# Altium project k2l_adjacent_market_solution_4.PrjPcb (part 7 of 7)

## Sheet system_power_03.SchDoc
size 431 x 279 mm; Date: Not shown in title block; ApprovedBy: Not shown in title block; CheckedBy: Not shown in title block; Author: Not shown in title block; CompanyName: Not shown in title block; Engineer: Not shown in title block; Organization: Not shown in title block; Address1: Not shown in title block; Address2: Not shown in title block; Address3: Not shown in title block; Address4: Not shown in title block; DocumentNumber: 36; Revision: Use project parameter SCH_Rev; SheetNumber: 36; SheetTotal: 38; PageSetup: Record=PageOptions¦CenterHorizontal=True¦CenterVertical=True¦PrintScale=1.00¦XCorrection=1.00¦YCorrection=1.00¦PrintKind=0¦BorderSize=5000000¦LeftOffset=0¦BottomOffset=0¦Orientation=2¦PaperLength=1000¦PaperWidth=1000¦Scale=100¦PaperSource=15¦PrintQuality=600¦MediaType=1¦DitherType=10¦PaperKind=Letter¦PrintScaleMode=1
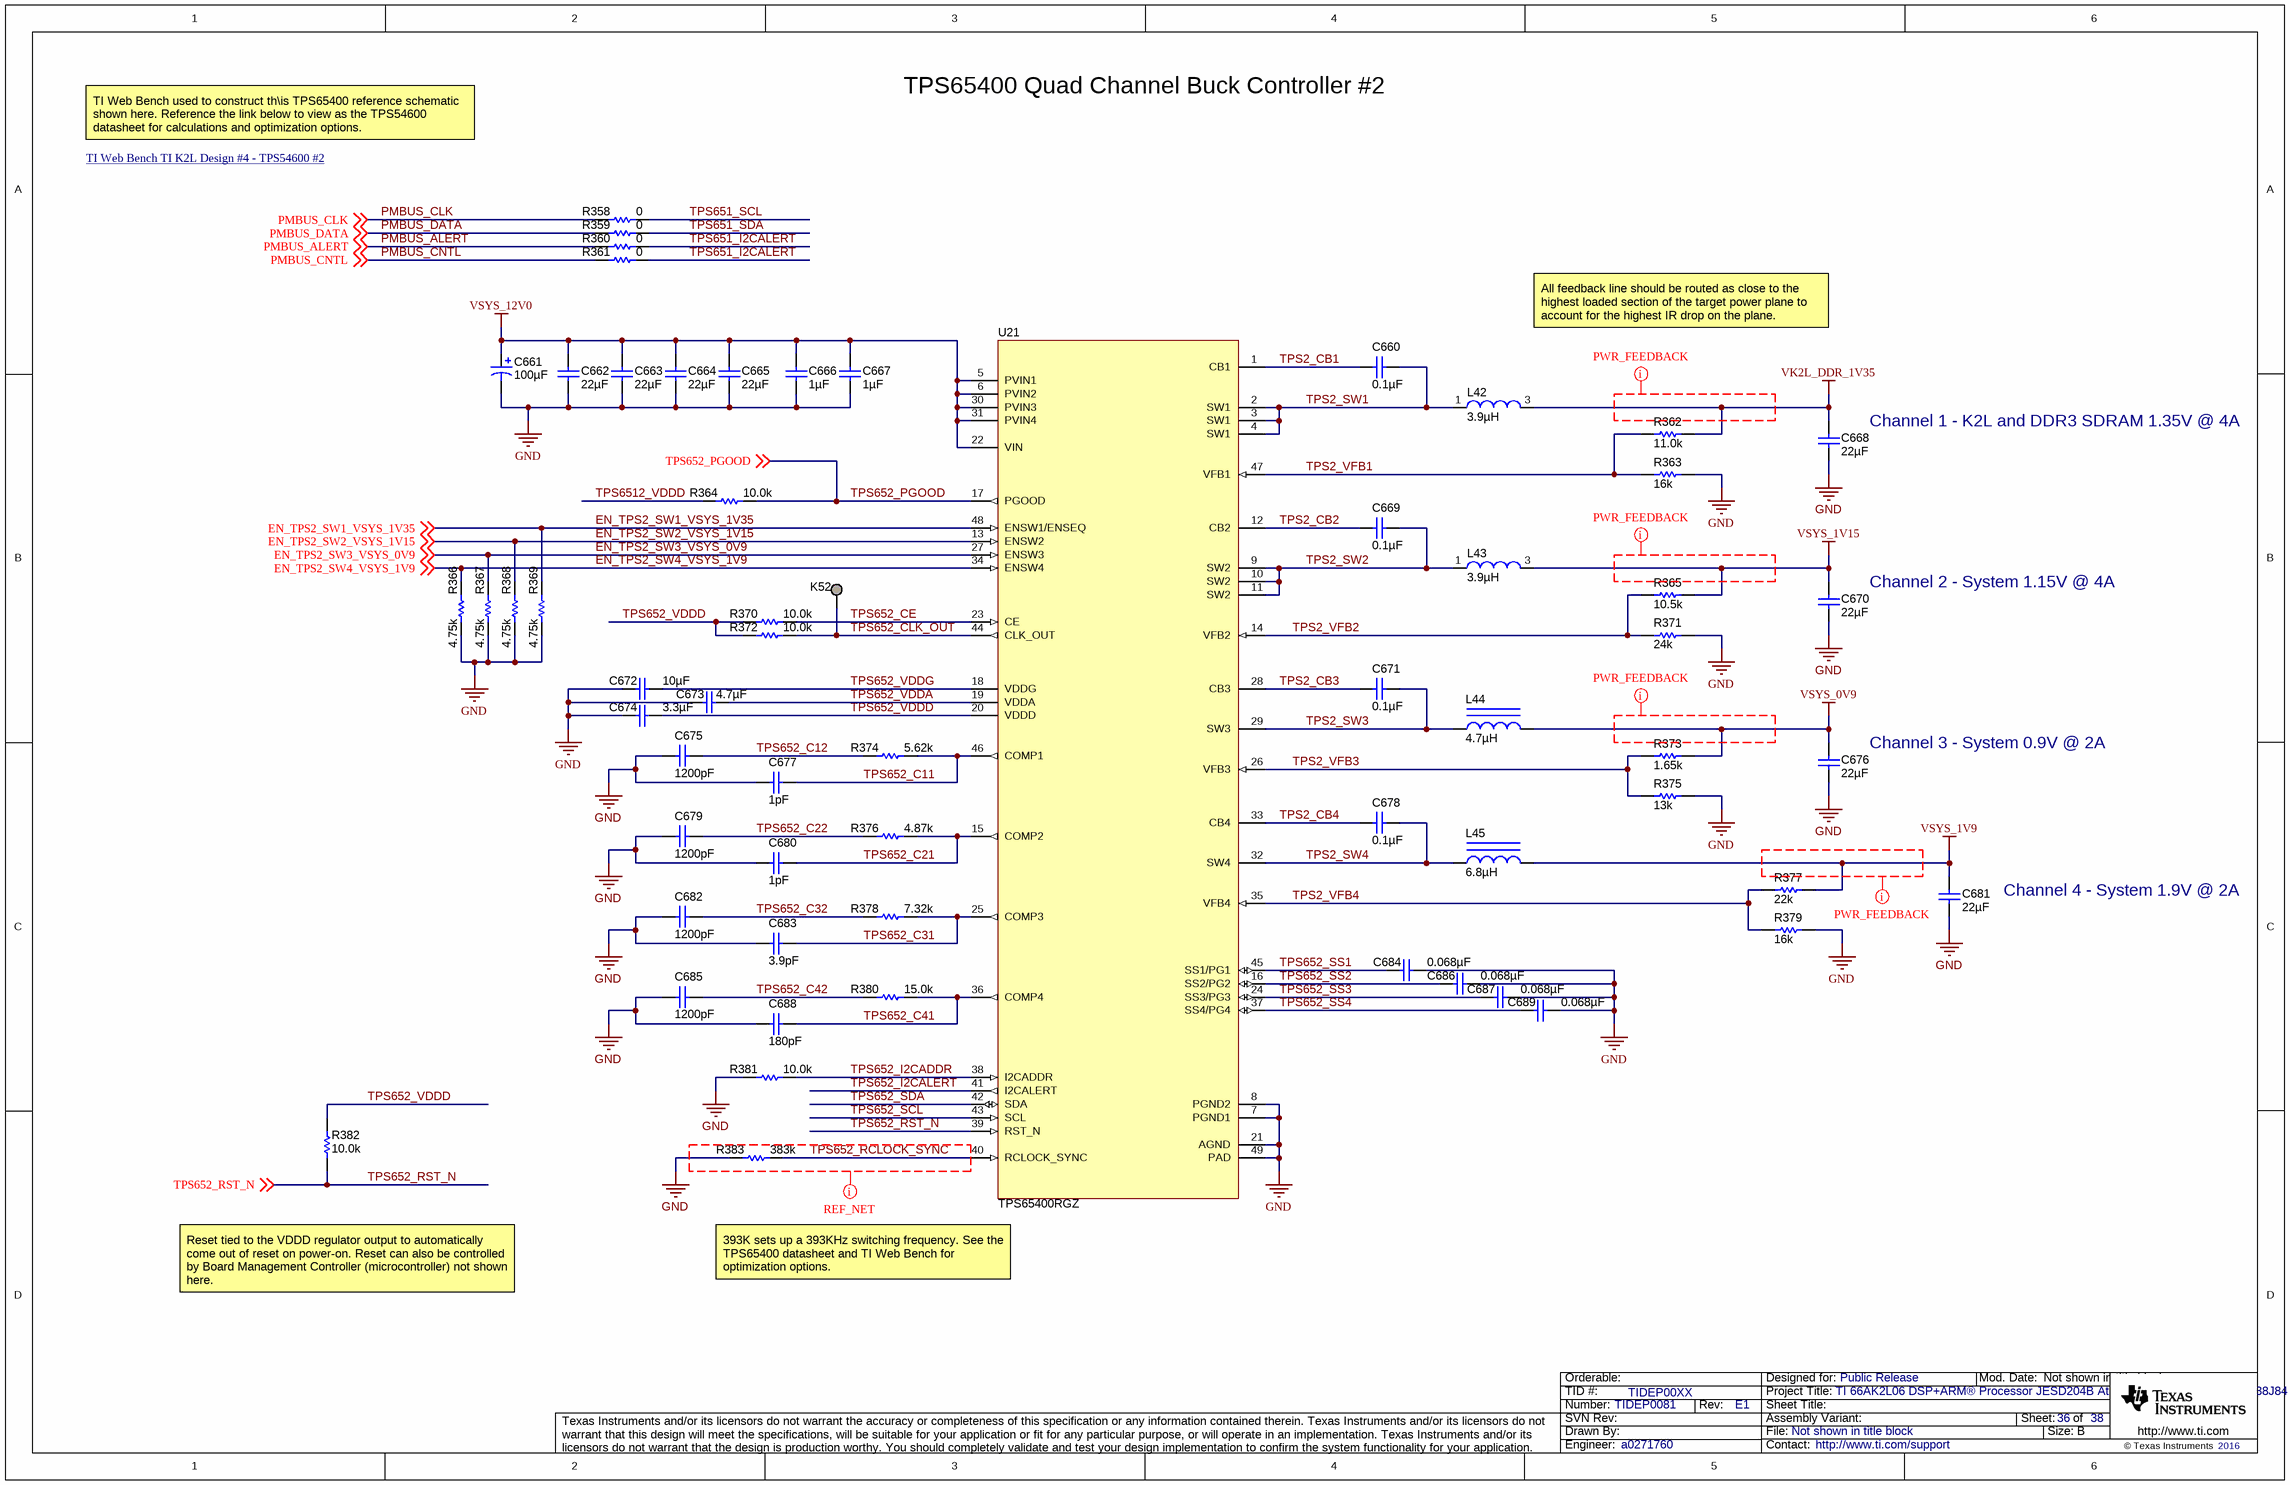
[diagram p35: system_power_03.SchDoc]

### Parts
C660  ValueDisplayed: 0.1µF  [0805_HV]  (hidden comment: 08053C104KAT2A)
C661  ValueDisplayed: 100µF  [6032-28]  (hidden comment: T495C107M006ATE150)
C662  ValueDisplayed: 22µF  [1210_270]  (hidden comment: GRM32ER61E226KE15L)
C663  ValueDisplayed: 22µF  [1210_270]  (hidden comment: GRM32ER61E226KE15L)
C664  ValueDisplayed: 22µF  [1210_270]  (hidden comment: GRM32ER61E226KE15L)
C665  ValueDisplayed: 22µF  [1210_270]  (hidden comment: GRM32ER61E226KE15L)
C666  ValueDisplayed: 1µF  [0603]  (hidden comment: GRM188R61E105KA12D)
C667  ValueDisplayed: 1µF  [0603]  (hidden comment: GRM188R61E105KA12D)
C668  ValueDisplayed: 22µF  [1210_270]  (hidden comment: GRM32ER61E226KE15L)
C669  ValueDisplayed: 0.1µF  [0805_HV]  (hidden comment: 08053C104KAT2A)
C670  ValueDisplayed: 22µF  [1210_270]  (hidden comment: GRM32ER61E226KE15L)
C671  ValueDisplayed: 0.1µF  [0805_HV]  (hidden comment: 08053C104KAT2A)
C672  ValueDisplayed: 10µF  [0603]  (hidden comment: GRM188R61E106MA73D)
C673  ValueDisplayed: 4.7µF  [0603]  (hidden comment: GRM188R61E475KE11D)
C674  ValueDisplayed: 3.3µF  [0603]  (hidden comment: GRM188R61A335KE15D)
C675  ValueDisplayed: 1200pF  [0402]  (hidden comment: GRM155R71H122KA01D)
C676  ValueDisplayed: 22µF  [1210_270]  (hidden comment: GRM32ER61E226KE15L)
C677  ValueDisplayed: 1pF  [0603]  (hidden comment: C0603C109C5GACTU)
C678  ValueDisplayed: 0.1µF  [0805_HV]  (hidden comment: 08053C104KAT2A)
C679  ValueDisplayed: 1200pF  [0402]  (hidden comment: GRM155R71H122KA01D)
C680  ValueDisplayed: 1pF  [0603]  (hidden comment: C0603C109C5GACTU)
C681  ValueDisplayed: 22µF  [1210_270]  (hidden comment: GRM32ER61E226KE15L)
C682  ValueDisplayed: 1200pF  [0402]  (hidden comment: GRM155R71H122KA01D)
C683  ValueDisplayed: 3.9pF  [0402]  (hidden comment: GRM1555C1H3R9CA01D)
C684  ValueDisplayed: 0.068µF  [0402]  (hidden comment: GRM155R61A683KA01D)
C685  ValueDisplayed: 1200pF  [0402]  (hidden comment: GRM155R71H122KA01D)
C686  ValueDisplayed: 0.068µF  [0402]  (hidden comment: GRM155R61A683KA01D)
C687  ValueDisplayed: 0.068µF  [0402]  (hidden comment: GRM155R61A683KA01D)
C688  ValueDisplayed: 180pF  [0402]  (hidden comment: GRM1555C1H181JA01D)
C689  ValueDisplayed: 0.068µF  [0402]  (hidden comment: GRM155R61A683KA01D)
K52  TESTPOINT  [TESTPOINT]  (value not drawn)  (no BOM)
L42  ValueDisplayed: 3.9µH  [WE-TPC_8043]  (hidden comment: 744071039)
L43  ValueDisplayed: 3.9µH  [WE-TPC_8043]  (hidden comment: 744071039)
L44  ValueDisplayed: 4.7µH  [IHSM5832]  (hidden comment: IHSM5832ER4R7L)
L45  ValueDisplayed: 6.8µH  [SRN6045]  (hidden comment: SRN6045-6R8Y)
R358  ValueDisplayed: 0  [0402]  (hidden comment: CRCW04020000Z0ED)
R359  ValueDisplayed: 0  [0402]  (hidden comment: CRCW04020000Z0ED)
R360  ValueDisplayed: 0  [0402]  (hidden comment: CRCW04020000Z0ED)
R361  ValueDisplayed: 0  [0402]  (hidden comment: CRCW04020000Z0ED)
R362  ValueDisplayed: 11.0k  [0402]  (hidden comment: CRCW040211K0FKED)
R363  ValueDisplayed: 16k  [0402]  (hidden comment: CRCW040216K0JNED)
R364  ValueDisplayed: 10.0k  [0402]  (hidden comment: CRCW040210K0FKED)
R365  ValueDisplayed: 10.5k  [0402]  (hidden comment: CRCW040210K5FKED)
R366  ValueDisplayed: 4.75k  [0402]  (hidden comment: CRCW04024K75FKED)
R367  ValueDisplayed: 4.75k  [0402]  (hidden comment: CRCW04024K75FKED)
R368  ValueDisplayed: 4.75k  [0402]  (hidden comment: CRCW04024K75FKED)
R369  ValueDisplayed: 4.75k  [0402]  (hidden comment: CRCW04024K75FKED)
R370  ValueDisplayed: 10.0k  [0402]  (hidden comment: CRCW040210K0FKED)
R371  ValueDisplayed: 24k  [0402]  (hidden comment: CRCW040224K0JNED)
R372  ValueDisplayed: 10.0k  [0402]  (hidden comment: CRCW040210K0FKED)
R373  ValueDisplayed: 1.65k  [0402]  (hidden comment: CRCW04021K65FKED)
R374  ValueDisplayed: 5.62k  [0402]  (hidden comment: CRCW04025K62FKED)
R375  ValueDisplayed: 13k  [0402]  (hidden comment: CRCW040213K0JNED)
R376  ValueDisplayed: 4.87k  [0402]  (hidden comment: CRCW04024K87FKED)
R377  ValueDisplayed: 22k  [0402]  (hidden comment: CRCW040222K0JNED)
R378  ValueDisplayed: 7.32k  [0402]  (hidden comment: CRCW04027K32FKED)
R379  ValueDisplayed: 16k  [0402]  (hidden comment: CRCW040216K0JNED)
R380  ValueDisplayed: 15.0k  [0402]  (hidden comment: CRCW040215K0FKED)
R381  ValueDisplayed: 10.0k  [0402]  (hidden comment: CRCW040210K0FKED)
R382  ValueDisplayed: 10.0k  [0402]  (hidden comment: CRCW040210K0FKED)
R383  ValueDisplayed: 383k  [0402]  (hidden comment: CRCW0402383KFKED)
U21  TPS65400RGZ  [RGZ0048G]

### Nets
GND: C661.2(-) C662.2 C663.2 C664.2 C665.2 C666.2 C667.2 C668.2 C670.2 C672.2 C673.1 C674.1 C675.2 C676.2 C677.2 C679.2 C680.2 C681.2 C682.2 C683.2 C684.2 C685.2 C686.2 C687.2 C688.2 C689.2 R363.2 R366.1 R367.1 R368.1 R369.1 R371.2 R375.2 R379.2 R381.1 R383.1 U21.7(PGND1) U21.8(PGND2) U21.21(AGND) U21.49(PAD)  [project net DAC_OUT0N_T1]
VK2L_DDR_1V35: C668.1 L42.3 R362.2
VSYS_0V9: C676.1 L44.2 R373.2
VSYS_1V9: C681.1 L45.2 R377.2
VSYS_1V15: C670.1 L43.3 R365.2
VSYS_12V0: C661.1(+) C662.1 C663.1 C664.1 C665.1 C666.1 C667.1 U21.5(PVIN1) U21.6(PVIN2) U21.22(VIN) U21.30(PVIN3) U21.31(PVIN4)
EN_TPS2_SW1_VSYS_1V35: R369.2 U21.48(ENSW1/ENSEQ) ; off-sheet EN_TPS2_SW1_VSYS_1V35
EN_TPS2_SW2_VSYS_1V15: R368.2 U21.13(ENSW2) ; off-sheet EN_TPS2_SW2_VSYS_1V15
EN_TPS2_SW3_VSYS_0V9: R367.2 U21.27(ENSW3) ; off-sheet EN_TPS2_SW3_VSYS_0V9
EN_TPS2_SW4_VSYS_1V9: R366.2 U21.34(ENSW4) ; off-sheet EN_TPS2_SW4_VSYS_1V9
PMBUS_ALERT: R360.1 ; off-sheet PMBUS_ALERT
PMBUS_CLK: R358.1 ; off-sheet PMBUS_CLK
PMBUS_CNTL: R361.1 ; off-sheet PMBUS_CNTL
PMBUS_DATA: R359.1 ; off-sheet PMBUS_DATA
TPS2_CB1: C660.2 U21.1(CB1)
TPS2_CB2: C669.2 U21.12(CB2)
TPS2_CB3: C671.2 U21.28(CB3)
TPS2_CB4: C678.2 U21.33(CB4)
TPS2_SW1: C660.1 L42.1 U21.2(SW1) U21.3(SW1) U21.4(SW1)
TPS2_SW2: C669.1 L43.1 U21.9(SW2) U21.10(SW2) U21.11(SW2)
TPS2_SW3: C671.1 L44.1 U21.29(SW3)
TPS2_SW4: C678.1 L45.1 U21.32(SW4)
TPS2_VFB1: R362.1 R363.1 U21.47(VFB1)
TPS2_VFB2: R365.1 R371.1 U21.14(VFB2)
TPS2_VFB3: R373.1 R375.1 U21.26(VFB3)
TPS2_VFB4: R377.1 R379.1 U21.35(VFB4)
TPS651_I2CALERT: R360.2 R361.2
TPS651_SCL: R358.2
TPS651_SDA: R359.2
TPS652_C11: C677.1 R374.2 U21.46(COMP1)
TPS652_C12: C675.1 R374.1
TPS652_C21: C680.1 R376.2 U21.15(COMP2)
TPS652_C22: C679.1 R376.1
TPS652_C31: C683.1 R378.2 U21.25(COMP3)
TPS652_C32: C682.1 R378.1
TPS652_C41: C688.1 R380.2 U21.36(COMP4)
TPS652_C42: C685.1 R380.1
TPS652_CE: R370.2 U21.23(CE)
TPS652_CLK_OUT: K52.1 R372.2 U21.44(CLK_OUT)
TPS652_I2CADDR: R381.2 U21.38(I2CADDR)
TPS652_I2CALERT: U21.41(I2CALERT)
TPS652_PGOOD: R364.2 U21.17(PGOOD) ; off-sheet TPS652_PGOOD
TPS652_RCLOCK_SYNC: R383.2 U21.40(RCLOCK_SYNC)
TPS652_RST_N: R382.1 U21.39(RST_N) ; off-sheet TPS652_RST_N
TPS652_SCL: U21.43(SCL)
TPS652_SDA: U21.42(SDA)
TPS652_SS1: C684.1 U21.45(SS1/PG1)
TPS652_SS2: C686.1 U21.16(SS2/PG2)
TPS652_SS3: C687.1 U21.24(SS3/PG3)
TPS652_SS4: C689.1 U21.37(SS4/PG4)
TPS652_VDDA: C673.2 U21.19(VDDA)
TPS652_VDDD: C674.2 R370.1 R372.1 R382.2 U21.20(VDDD)
TPS652_VDDG: C672.1 U21.18(VDDG)
TPS6512_VDDD: R364.1

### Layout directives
net class Undefined: (no net found under the mark), TPS652_RCLOCK_SYNC

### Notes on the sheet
- TPS65400 Quad Channel Buck Controller #2
- TI Web Bench used to construct th\is TPS65400 reference schematic shown here. Reference the link below to view as the TPS54600 datasheet for calculations and optimization options.
- TI Web Bench TI K2L Design #4 - TPS54600 #2 <https://webench.ti.com/wb5/OpenPublicSharedProject.jsp?id=085F10CA9CD21835&s=c>
- All feedback line should be routed as close to the highest loaded section of the target power plane to account for the highest IR drop on the plane.
- (near C668) Channel 1 - K2L and DDR3 SDRAM 1.35V @ 4A
- (near C670) Channel 2 - System 1.15V @ 4A
- (near C676) Channel 3 - System 0.9V @ 2A
- Channel 4 - System 1.9V @ 2A
- Reset tied to the VDDD regulator output to automatically come out of reset on power-on. Reset can also be controlled by Board Management Controller (microcontroller) not shown here.
- 393K sets up a 393KHz switching frequency. See the TPS65400 datasheet and TI Web Bench for optimization options.

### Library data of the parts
C660 C669 C671 C678 = 08053C104KAT2A: CAP, CERM, 0.1 µF, 25 V, +/- 10%, X7R, 0805; Manufacturer: AVX; Polarized: N; CompType: Capacitor; Value: 0.1uF; U/M: EA; Cap_F: 0.0000001; Tolerance_%: 10; ESR_ohm: 0.28; Value1: 0.28 ohm; VDC_V: 25; Value2: 25V; TaMin_C: -55; TaMax_C: 125; Cap_Case: 0805; SizeArea_mm2: 2.5; SizeAreaWB_mm2: 6.75; SizeX_mm: 2; SizeY_mm: 1.25; SizeZ_mm: 1.45; AEC Category: Q200
C661 = T495C107M006ATE150: CAP, TA, 100 µF, 6.3 V, +/- 20%, 0.15 ohm, SMD; Manufacturer: Kemet; Polarized: Y; CompType: Capacitor; Value: 100uF; U/M: EA; Cap_F: 0.0001; Tolerance_%: 20; VDC_V: 6.3; Value2: 6.3V; ESR_ohm: 0.15; IRMS_A: 0.77; TaMin_C: -55; TaMax_C: 125; Cap_Case: C; AEC Category: Q200
C662-C665 C668 C670 C676 C681 = GRM32ER61E226KE15L: CAP, CERM, 22 µF, 25 V, +/- 10%, X5R, 1210; Manufacturer: MuRata; Polarized: N; CompType: Capacitor; Value: 22uF; U/M: EA; Cap_F: 0.000022; Tolerance_%: 10; ESR_ohm: 0.002; Value1: 0.002 ohm; VDC_V: 25; Value2: 25V; IRMS_A: 3.67; TaMin_C: -55; TaMax_C: 85; Cap_Case: 1210; SizeArea_mm2: 8; SizeAreaWB_mm2: 14.7; SizeX_mm: 3.2; SizeY_mm: 2.5; SizeZ_mm: 2.7; AEC Category: Q200
C666 C667 = GRM188R61E105KA12D: CAP, CERM, 1 µF, 25 V, +/- 10%, X5R, 0603; Manufacturer: MuRata; Polarized: N; CompType: Capacitor; Value: 1uF; U/M: EA; Cap_F: 0.000001; Tolerance_%: 10; Value1: Unknown; VDC_V: 25; Value2: 25V; TaMin_C: -55; TaMax_C: 85; SizeArea_mm2: 1.28; SizeAreaWB_mm2: 4.68; SizeX_mm: 1.6; SizeY_mm: 0.8; SizeZ_mm: 1; AEC Category: Q200
C672 = GRM188R61E106MA73D: CAP, CERM, 10 µF, 25 V, +/- 20%, X5R, 0603; Manufacturer: MuRata; Polarized: N; CompType: Capacitor; Value: 10uF; U/M: EA; Cap_F: 0.00001; Tolerance_%: 20; Value1: Unknown; VDC_V: 25; Value2: 25V; TaMin_C: -55; TaMax_C: 85; SizeArea_mm2: 1.28; SizeAreaWB_mm2: 4.68; SizeX_mm: 1.6; SizeY_mm: 0.8; SizeZ_mm: 1; AEC Category: Q200
C673 = GRM188R61E475KE11D: CAP, CERM, 4.7 µF, 25 V, +/- 10%, X5R, 0603; Manufacturer: MuRata; Polarized: N; CompType: Capacitor; Value: 4.7uF; U/M: EA; Cap_F: 0.0000047; Tolerance_%: 10; Value1: Unknown; VDC_V: 25; Value2: 25V; TaMin_C: -55; TaMax_C: 85; SizeArea_mm2: 1.28; SizeAreaWB_mm2: 4.68; SizeX_mm: 1.6; SizeY_mm: 0.8; SizeZ_mm: 1; AEC Category: Q200
C674 = GRM188R61A335KE15D: CAP, CERM, 3.3 µF, 10 V, +/- 10%, X5R, 0603; Manufacturer: MuRata; Polarized: N; CompType: Capacitor; Value: 3.3uF; U/M: EA; Cap_F: 0.0000033; Tolerance_%: 10; ESR_ohm: 0.005; Value1: 0.005 ohm; Value2: 10V; IRMS_A: 1.7; TaMin_C: -55; TaMax_C: 85; SizeArea_mm2: 1.28; SizeAreaWB_mm2: 4.68; SizeX_mm: 1.6; SizeY_mm: 0.8; SizeZ_mm: 1; AEC Category: Q200
C675 C679 C682 C685 = GRM155R71H122KA01D: CAP, CERM, 1200 pF, 50 V, +/- 10%, X7R, 0402; Manufacturer: MuRata; Polarized: N; CompType: Capacitor; Value: 1200pF; U/M: EA; Cap_F: 0.0000000012; Tolerance_%: 10; Value1: Unknown; VDC_V: 50; Value2: 50V; TaMin_C: -55; TaMax_C: 125; SizeArea_mm2: 0.5; SizeAreaWB_mm2: 3; SizeX_mm: 1; SizeZ_mm: 0.6; AEC Category: Q200
C677 C680 = C0603C109C5GACTU: CAP, CERM, 1 pF, 50 V, +/- 25%, C0G/NP0, 0603; Manufacturer: Kemet; Polarized: N; CompType: Capacitor; Value: 1pF; U/M: EA; Cap_F: 0.000000000001; Tolerance_%: 25; Value1: Unknown; VDC_V: 50; Value2: 50V; TaMin_C: -55; TaMax_C: 125; SizeArea_mm2: 1.28; SizeAreaWB_mm2: 4.68; SizeX_mm: 1.6; SizeY_mm: 0.8; SizeZ_mm: 1; AEC Category: Q200
C683 = GRM1555C1H3R9CA01D: CAP, CERM, 3.9 pF, 50 V, +/- 5%, C0G/NP0, 0402; Manufacturer: MuRata; Polarized: N; CompType: Capacitor; Value: 3.9pF; U/M: EA; Cap_F: 0.0000000000039; Tolerance_%: 5; Value1: Unknown; VDC_V: 50; Value2: 50V; TaMin_C: -55; TaMax_C: 125; SizeArea_mm2: 0.5; SizeAreaWB_mm2: 3; SizeX_mm: 1; SizeZ_mm: 0.6; AEC Category: Q200
C684 C686 C687 C689 = GRM155R61A683KA01D: CAP, CERM, 0.068 µF, 10 V, +/- 10%, X5R, 0402; Manufacturer: MuRata; Polarized: N; CompType: Capacitor; Value: 0.068uF; U/M: EA; Cap_F: 0.000000068; Tolerance_%: 10; Value1: Unknown; Value2: 10V; TaMin_C: -55; TaMax_C: 85; SizeArea_mm2: 0.5; SizeAreaWB_mm2: 3; SizeX_mm: 1; SizeZ_mm: 0.6; AEC Category: Q200
C688 = GRM1555C1H181JA01D: CAP, CERM, 180 pF, 50 V, +/- 5%, C0G/NP0, 0402; Manufacturer: MuRata; Polarized: N; CompType: Capacitor; Value: 180pF; U/M: EA; Cap_F: 0.00000000018; Tolerance_%: 5; Value1: Unknown; VDC_V: 50; Value2: 50V; TaMin_C: -55; TaMax_C: 125; SizeArea_mm2: 0.5; SizeAreaWB_mm2: 3; SizeX_mm: 1; SizeZ_mm: 0.6; AEC Category: Q200
K52 = TESTPOINT: TEST POINT.  No entry in BOM.
L42 L43 = 744071039: Inductor, Shielded Drum Core, Metal Composite, 3.9 µH, 4.9 A, 0.013 ohm, SMD; Manufacturer: Wurth Elektronik; SymbolCreator: a0411947; Ind_H: 3.9E-6; Value: 3.9uH; Imax_A: 4.9; Irms: 4.9A @ 40C rise; Isat: 5A @ 35% inductance drop; DCR_ohm: 0.013; Value2: 4.9A; AEC Category: Q200
L44 = IHSM5832ER4R7L: Inductor, Shielded Drum Core, Ferrite, 4.7 µH, 2.8 A, 0.023 ohm, SMD; Manufacturer: Vishay-Dale; Value: 4.7uH; Ind_H: 4.7E-6; Imax_A: 2.8; Irms: 7.4A @ 40C rise; Isat: 2.8A @ 5% inductance drop; DCR_ohm: 0.023; Value2: 2.8A; AEC Category: Q200
L45 = SRN6045-6R8Y: Inductor, Drum Core, Ferrite, 6.8 µH, 2.8 A, 0.0473 ohm, SMD; Manufacturer: Bourns; Value: 6.8uH; Ind_H: 6.8E-6; Imax_A: 2.8; Irms: 2.8A @ 40C rise; Isat: 3.8A @ 30% inductance drop; DCR_ohm: 0.0473; Value2: 2.8A; AEC Category: Q200
R358-R361 = CRCW04020000Z0ED: RES, 0, 5%, 0.063 W, 0402; Manufacturer: Vishay-Dale; CompType: Resistor; Value: 0; Value_Code: 0000; Tolerance_%: 5; Power_W: 0.063; Value2: 0.063W; VDC_V: 50; TempCo: 200 ppm/C; SizeArea_mm2: 0.5; SizeX_mm: 1; SizeZ_mm: 0.6; EIA_Code: E24; U/M: EA; AEC Category: Q200
R362 = CRCW040211K0FKED: RES, 11.0 k, 1%, 0.063 W, 0402; Manufacturer: Vishay-Dale; CompType: Resistor; Value: 11.0k; Res_ohm: 11000; Value_Code: 11k0; Tolerance_%: 1; Power_W: 0.063; Value2: 0.063W; VDC_V: 50; TempCo: 100 ppm/C; SizeArea_mm2: 0.5; SizeZ_mm: 0.6; EIA_Code: E96; U/M: EA; AEC Category: Q200
R363 R379 = CRCW040216K0JNED: RES, 16 k, 5%, 0.063 W, 0402; Manufacturer: Vishay-Dale; CompType: Resistor; Value: 16k; Res_ohm: 16000; Value_Code: 16k0; Tolerance_%: 5; Power_W: 0.063; Value2: 0.063W; VDC_V: 50; TempCo: 200 ppm/C; SizeArea_mm2: 0.5; SizeX_mm: 1; SizeZ_mm: 0.6; EIA_Code: E24; U/M: EA; AEC Category: Q200
R364 R370 R372 R381 R382 = CRCW040210K0FKED: RES, 10.0 k, 1%, 0.063 W, 0402; Manufacturer: Vishay-Dale; CompType: Resistor; Value: 10.0k; Res_ohm: 10000; Value_Code: 10k0; Tolerance_%: 1; Power_W: 0.063; Value2: 0.063W; VDC_V: 50; TempCo: 100 ppm/C; EIA_Code: E96; U/M: EA
R365 = CRCW040210K5FKED: RES, 10.5 k, 1%, 0.063 W, 0402; Manufacturer: Vishay-Dale; CompType: Resistor; Value: 10.5k; Res_ohm: 10500; Value_Code: 10k5; Tolerance_%: 1; Power_W: 0.063; Value2: 0.063W; VDC_V: 50; TempCo: 100 ppm/C; SizeArea_mm2: 0.5; SizeZ_mm: 0.6; EIA_Code: E96; U/M: EA; AEC Category: Q200
R366-R369 = CRCW04024K75FKED: RES, 4.75 k, 1%, 0.063 W, 0402; Manufacturer: Vishay-Dale; CompType: Resistor; Value: 4.75k; Res_ohm: 4750; Value_Code: 4k75; Tolerance_%: 1; Power_W: 0.063; Value2: 0.063W; VDC_V: 50; TempCo: 100 ppm/C; EIA_Code: E96; U/M: EA
R371 = CRCW040224K0JNED: RES, 24 k, 5%, 0.063 W, 0402; Manufacturer: Vishay-Dale; CompType: Resistor; Value: 24k; Res_ohm: 24000; Value_Code: 24k0; Tolerance_%: 5; Power_W: 0.063; Value2: 0.063W; VDC_V: 50; TempCo: 200 ppm/C; SizeArea_mm2: 0.5; SizeX_mm: 1; SizeZ_mm: 0.6; EIA_Code: E24; U/M: EA; AEC Category: Q200
R373 = CRCW04021K65FKED: RES, 1.65 k, 1%, 0.063 W, 0402; Manufacturer: Vishay-Dale; CompType: Resistor; Value: 1.65k; Res_ohm: 1650; Value_Code: 1k65; Tolerance_%: 1; Power_W: 0.063; Value2: 0.063W; VDC_V: 50; TempCo: 100 ppm/C; SizeArea_mm2: 0.5; SizeZ_mm: 0.6; EIA_Code: E96; U/M: EA; AEC Category: Q200
R374 = CRCW04025K62FKED: RES, 5.62 k, 1%, 0.063 W, 0402; Manufacturer: Vishay-Dale; CompType: Resistor; Value: 5.62k; Res_ohm: 5620; Value_Code: 5k62; Tolerance_%: 1; Power_W: 0.063; Value2: 0.063W; VDC_V: 50; TempCo: 100 ppm/C; SizeArea_mm2: 0.5; SizeZ_mm: 0.6; EIA_Code: E96; U/M: EA; AEC Category: Q200
R375 = CRCW040213K0JNED: RES, 13 k, 5%, 0.063 W, 0402; Manufacturer: Vishay-Dale; CompType: Resistor; Value: 13k; Res_ohm: 13000; Value_Code: 13k0; Tolerance_%: 5; Power_W: 0.063; Value2: 0.063W; VDC_V: 50; TempCo: 200 ppm/C; SizeArea_mm2: 0.5; SizeX_mm: 1; SizeZ_mm: 0.6; EIA_Code: E24; U/M: EA; AEC Category: Q200
R376 = CRCW04024K87FKED: RES, 4.87 k, 1%, 0.063 W, 0402; Manufacturer: Vishay-Dale; CompType: Resistor; Value: 4.87k; Res_ohm: 4870; Value_Code: 4k87; Tolerance_%: 1; Power_W: 0.063; Value2: 0.063W; VDC_V: 50; TempCo: 100 ppm/C; SizeArea_mm2: 0.5; SizeZ_mm: 0.6; EIA_Code: E96; U/M: EA; AEC Category: Q200
R377 = CRCW040222K0JNED: RES, 22 k, 5%, 0.063 W, 0402; Manufacturer: Vishay-Dale; CompType: Resistor; Value: 22k; Res_ohm: 22000; Value_Code: 22k0; Tolerance_%: 5; Power_W: 0.063; Value2: 0.063W; VDC_V: 50; TempCo: 200 ppm/C; SizeArea_mm2: 0.5; SizeX_mm: 1; SizeZ_mm: 0.6; EIA_Code: E24; U/M: EA; AEC Category: Q200
R378 = CRCW04027K32FKED: RES, 7.32 k, 1%, 0.063 W, 0402; Manufacturer: Vishay-Dale; CompType: Resistor; Value: 7.32k; Res_ohm: 7320; Value_Code: 7k32; Tolerance_%: 1; Power_W: 0.063; Value2: 0.063W; VDC_V: 50; TempCo: 100 ppm/C; SizeArea_mm2: 0.5; SizeZ_mm: 0.6; EIA_Code: E96; U/M: EA; AEC Category: Q200
R380 = CRCW040215K0FKED: RES, 15.0 k, 1%, 0.063 W, 0402; Manufacturer: Vishay-Dale; CompType: Resistor; Value: 15.0k; Res_ohm: 15000; Value_Code: 15k0; Tolerance_%: 1; Power_W: 0.063; Value2: 0.063W; VDC_V: 50; TempCo: 100 ppm/C; SizeArea_mm2: 0.5; SizeZ_mm: 0.6; EIA_Code: E96; U/M: EA; AEC Category: Q200
R383 = CRCW0402383KFKED: RES, 383 k, 1%, 0.063 W, 0402; Manufacturer: Vishay-Dale; CompType: Resistor; Value: 383k; Res_ohm: 383000; Tolerance_%: 1; Power_W: 0.063; Value2: 0.063W; VDC_V: 50; TempCo: 100 ppm/C; SizeArea_mm2: 0.5; SizeZ_mm: 0.6; EIA_Code: E96; U/M: EA; AEC Category: Q200
U21 = TPS65400RGZ: 4.5V TO 18V INPUT FLEXIBLE POWER MANAGEMENT UNIT WITH PMBus/ I2C AND INTEGRATED SEQUENCING, RGZ0048G; Manufacturer: Texas Instruments; SymbolCreator: a0411947; CompType: IC; U/M: EA

## Sheet system_power_04.SchDoc
size 431 x 279 mm; Date: Not shown in title block; ApprovedBy: Not shown in title block; CheckedBy: Not shown in title block; Author: Not shown in title block; CompanyName: Not shown in title block; Engineer: Not shown in title block; Organization: Not shown in title block; Address1: Not shown in title block; Address2: Not shown in title block; Address3: Not shown in title block; Address4: Not shown in title block; DocumentNumber: 37; Revision: Use project parameter SCH_Rev; SheetNumber: 37; SheetTotal: 38; PageSetup: Record=PageOptions¦CenterHorizontal=True¦CenterVertical=True¦PrintScale=1.00¦XCorrection=1.00¦YCorrection=1.00¦PrintKind=0¦BorderSize=5000000¦LeftOffset=0¦BottomOffset=0¦Orientation=2¦PaperLength=1000¦PaperWidth=1000¦Scale=100¦PaperSource=15¦PrintQuality=600¦MediaType=1¦DitherType=10¦PaperKind=Letter¦PrintScaleMode=1
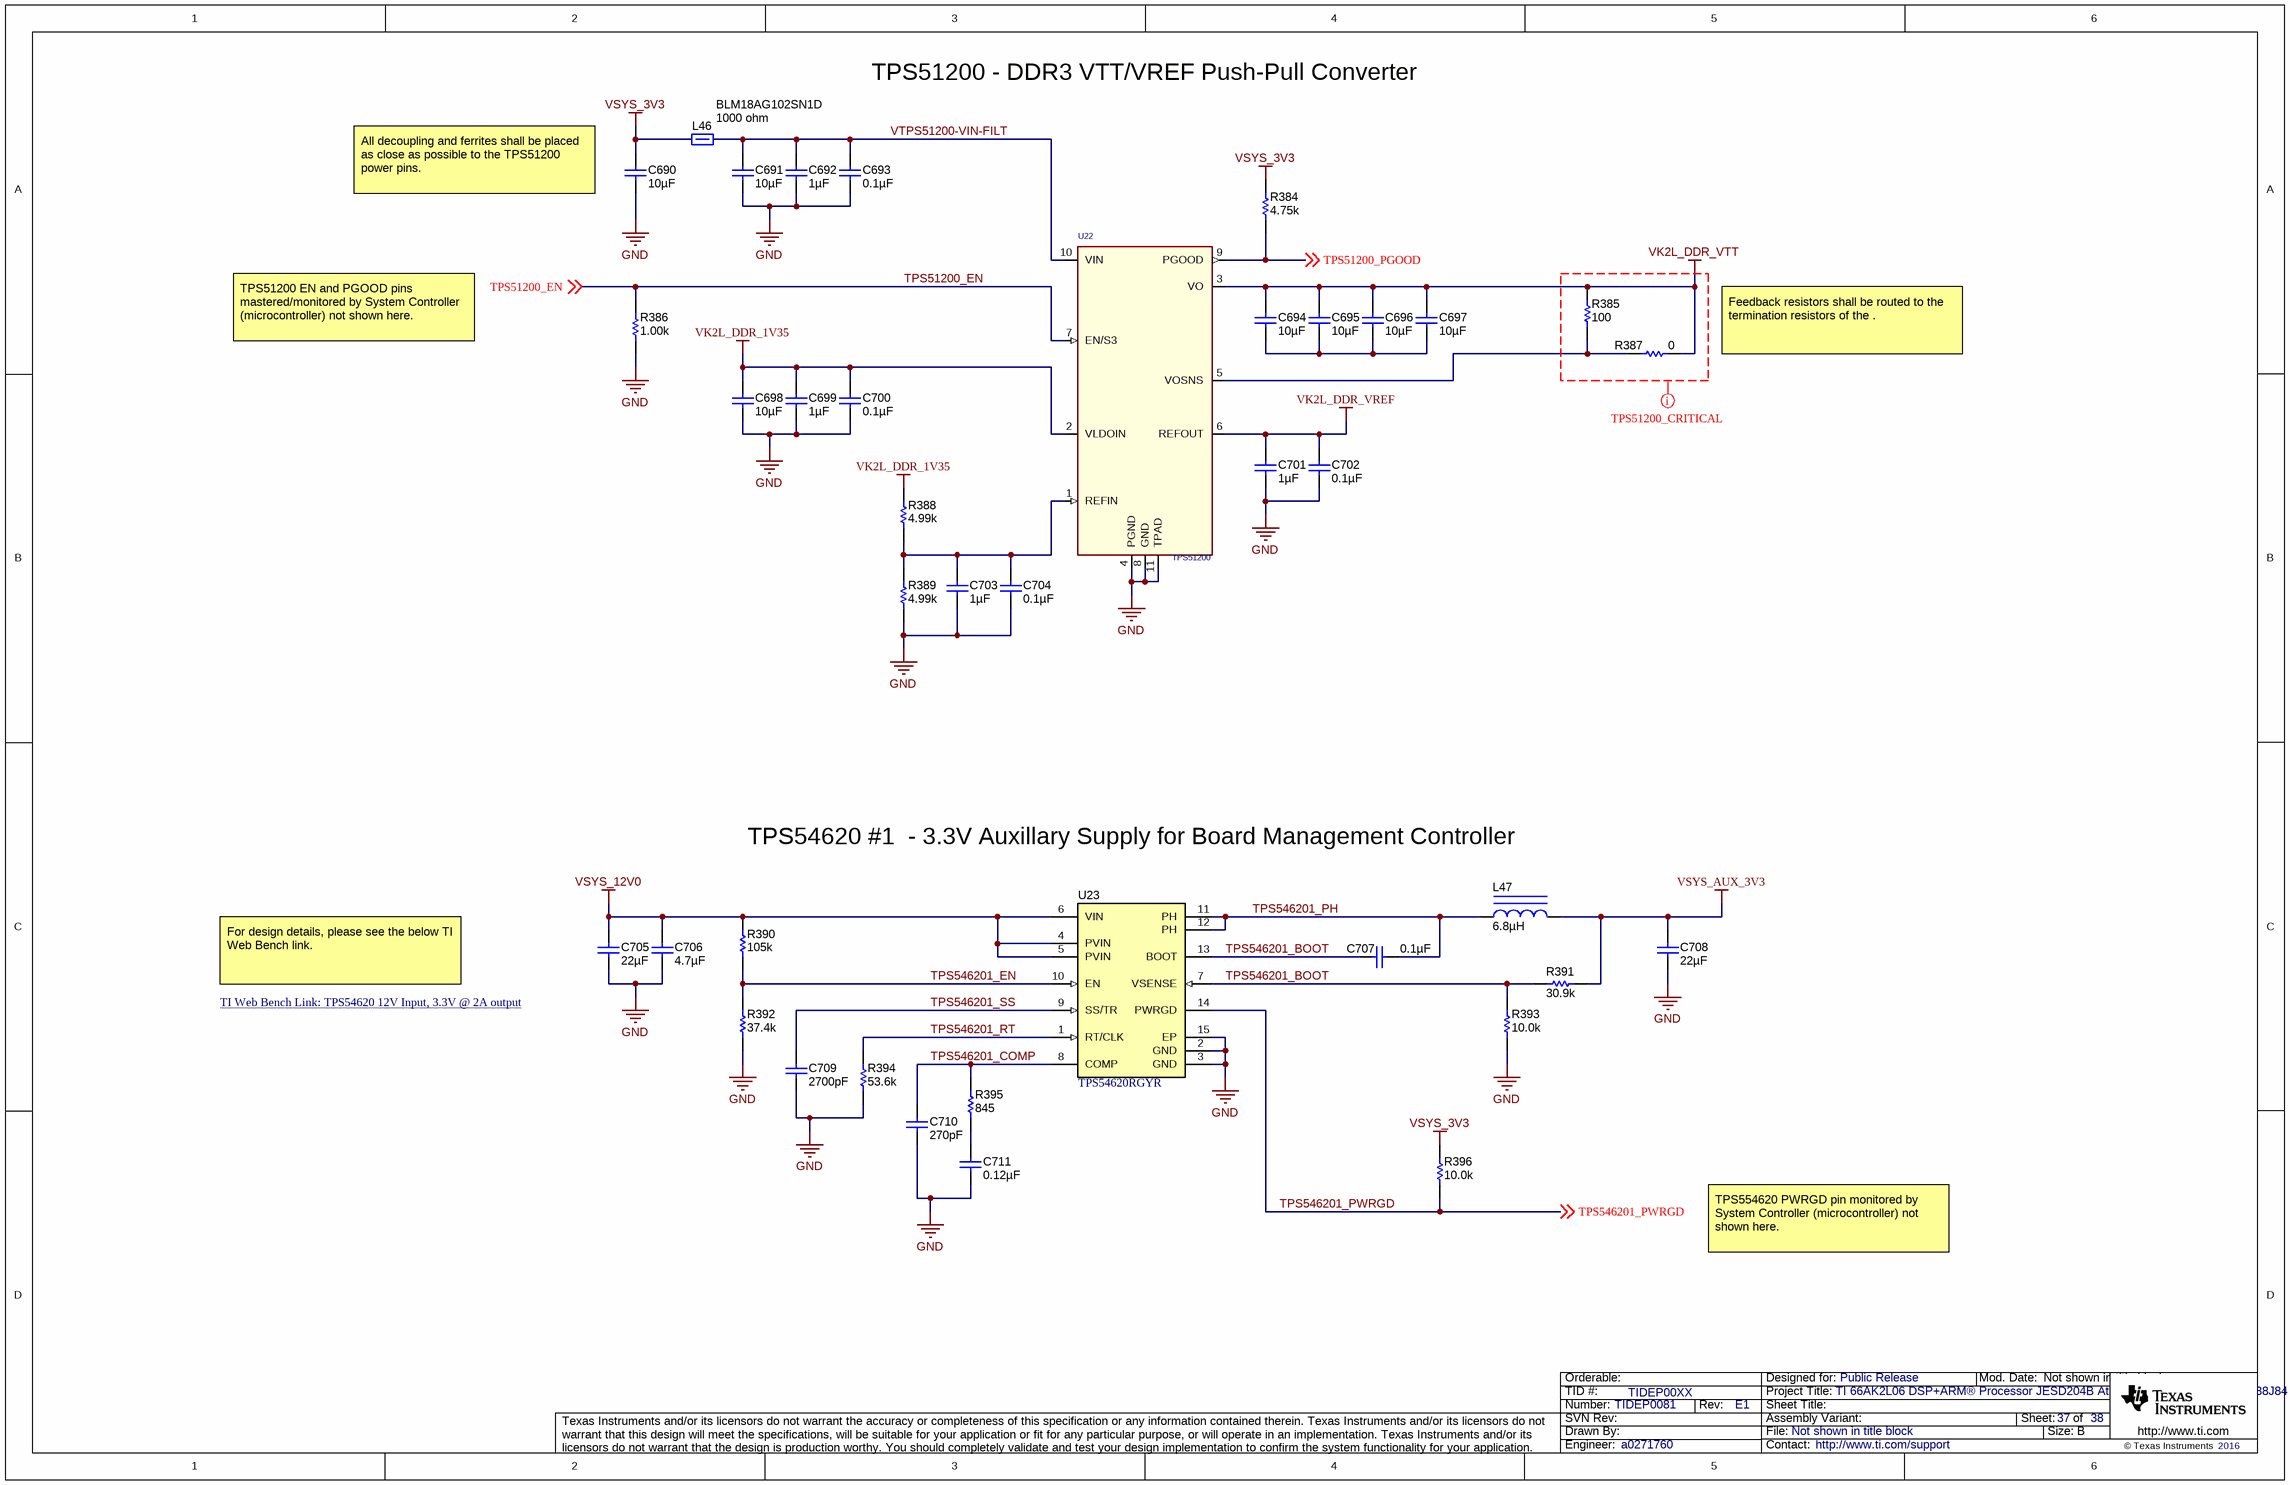
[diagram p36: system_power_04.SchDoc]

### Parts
C690  ValueDisplayed: 10µF  [0805_HV]  (hidden comment: GRM21BF50J106ZE01L)
C691  ValueDisplayed: 10µF  [0805_HV]  (hidden comment: GRM21BF50J106ZE01L)
C692  ValueDisplayed: 1µF  [0603]  (hidden comment: GRM188R70J105KA01D)
C693  ValueDisplayed: 0.1µF  [0603]  (hidden comment: GRM188R70J104KA01D)
C694  ValueDisplayed: 10µF  [0805_HV]  (hidden comment: GRM21BF50J106ZE01L)
C695  ValueDisplayed: 10µF  [0805_HV]  (hidden comment: GRM21BF50J106ZE01L)
C696  ValueDisplayed: 10µF  [0805_HV]  (hidden comment: GRM21BF50J106ZE01L)
C697  ValueDisplayed: 10µF  [0805_HV]  (hidden comment: GRM21BF50J106ZE01L)
C698  ValueDisplayed: 10µF  [0805_HV]  (hidden comment: GRM21BF50J106ZE01L)
C699  ValueDisplayed: 1µF  [0603]  (hidden comment: GRM188R70J105KA01D)
C700  ValueDisplayed: 0.1µF  [0603]  (hidden comment: GRM188R70J104KA01D)
C701  ValueDisplayed: 1µF  [0603]  (hidden comment: GRM188R70J105KA01D)
C702  ValueDisplayed: 0.1µF  [0603]  (hidden comment: GRM188R70J104KA01D)
C703  ValueDisplayed: 1µF  [0603]  (hidden comment: GRM188R70J105KA01D)
C704  ValueDisplayed: 0.1µF  [0603]  (hidden comment: GRM188R70J104KA01D)
C705  ValueDisplayed: 22µF  [1210_270]  (hidden comment: GRM32ER61E226KE15L)
C706  ValueDisplayed: 4.7µF  [0805_HV]  (hidden comment: GRM21BR61E475KA12L)
C707  ValueDisplayed: 0.1µF  [0805_HV]  (hidden comment: 08053C104KAT2A)
C708  ValueDisplayed: 22µF  [1210_270]  (hidden comment: GRM32ER61E226KE15L)
C709  ValueDisplayed: 2700pF  [0805_HV]  (hidden comment: CC0805KRX7R9BB272)
C710  ValueDisplayed: 270pF  [0402]  (hidden comment: GRM1555C1H271FA01D)
C711  ValueDisplayed: 0.12µF  [0402]  (hidden comment: GRM155C80J124KE01D)
L46  BLM18AG102SN1D  value 1000 ohm  [0603]
L47  ValueDisplayed: 6.8µH  [SRN6045]  (hidden comment: SRN6045-6R8Y)
R384  ValueDisplayed: 4.75k  [0402]  (hidden comment: CRCW04024K75FKED)
R385  ValueDisplayed: 100  [0402]  (hidden comment: CRCW0402100RFKED)
R386  ValueDisplayed: 1.00k  [0402]  (hidden comment: CRCW04021K00FKED)
R387  ValueDisplayed: 0  [0402]  (hidden comment: CRCW04020000Z0ED)
R388  ValueDisplayed: 4.99k  [0402]  (hidden comment: CRCW04024K99FKED)
R389  ValueDisplayed: 4.99k  [0402]  (hidden comment: CRCW04024K99FKED)
R390  ValueDisplayed: 105k  [0402]  (hidden comment: CRCW0402105KFKED)
R391  ValueDisplayed: 30.9k  [0402]  (hidden comment: CRCW040230K9FKED)
R392  ValueDisplayed: 37.4k  [0402]  (hidden comment: CRCW040237K4FKED)
R393  ValueDisplayed: 10.0k  [0402]  (hidden comment: CRCW040210K0DHEDP)
R394  ValueDisplayed: 53.6k  [0402]  (hidden comment: CRCW040253K6FKED)
R395  ValueDisplayed: 845  [0402]  (hidden comment: CRCW0402845RFKED)
R396  ValueDisplayed: 10.0k  [0402]  (hidden comment: CRCW040210K0DHEDP)
U22  TPS51200  [MSOP-10]
U23  TPS54620RGYR  [RHL0014A]

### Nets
GND: C690.2 C691.2 C692.2 C693.2 C698.2 C699.2 C700.2 C701.2 C702.2 C703.2 C704.2 C705.2 C706.2 C708.2 C709.2 C710.2 C711.2 R386.1 R389.1 R392.1 R393.1 R394.1 U22.4(PGND) U22.8(GND) U22.11(TPAD) U23.2(GND) U23.3(GND) U23.15(EP)  [project net DAC_OUT0N_T1]
VK2L_DDR_1V35: C698.1 C699.1 C700.1 R388.2 U22.2(VLDOIN)
VK2L_DDR_VREF: C701.1 C702.1 U22.6(REFOUT)
VK2L_DDR_VTT: C694.1 C695.1 C696.1 C697.1 R385.1 R387.1 U22.3(VO)
VSYS_3V3: C690.1 L46.1 R384.2 R396.2
VSYS_12V0: C705.1 C706.1 R390.2 U23.4(PVIN) U23.5(PVIN) U23.6(VIN)
VSYS_AUX_3V3: C708.1 L47.2 R391.2
TPS51200_EN: R386.2 U22.7(EN/S3) ; off-sheet TPS51200_EN
TPS51200_PGOOD: R384.1 U22.9(PGOOD) ; off-sheet TPS51200_PGOOD
TPS546201_BOOT: C707.2 R391.1 R393.2 U23.7(VSENSE) U23.13(BOOT)
TPS546201_COMP: C710.1 R395.2 U23.8(COMP)
TPS546201_EN: R390.1 R392.2 U23.10(EN)
TPS546201_PH: C707.1 L47.1 U23.11(PH) U23.12(PH)
TPS546201_PWRGD: R396.1 U23.14(PWRGD) ; off-sheet TPS546201_PWRGD
TPS546201_RT: R394.2 U23.1(RT/CLK)
TPS546201_SS: C709.1 U23.9(SS/TR)
VTPS51200-VIN-FILT: C691.1 C692.1 C693.1 L46.2 U22.10(VIN)
NetC694_2: C694.2 C695.2 C696.2 C697.2
NetC703_1: C703.1 C704.1 R388.1 R389.2 U22.1(REFIN)
NetC711_1: C711.1 R395.1
NetR385_2: R385.2 R387.2 U22.5(VOSNS)

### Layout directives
net class Undefined: VK2L_DDR_VTT

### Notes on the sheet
- TPS51200 - DDR3 VTT/VREF Push-Pull Converter
- (near C690) All decoupling and ferrites shall be placed as close as possible to the TPS51200 power pins.
- TPS51200 EN and PGOOD pins mastered/monitored by System Controller (microcontroller) not shown here.
- Feedback resistors shall be routed to the termination resistors of the .
- TPS54620 #1  - 3.3V Auxillary Supply for Board Management Controller
- For design details, please see the below TI Web Bench link.
- TI Web Bench Link: TPS54620 12V Input, 3.3V @ 2A output <https://webench.ti.com/appinfo/webench/scripts/SDP.cgi?ID=4D9808AAF39DD68E>
- TPS554620 PWRGD pin monitored by System Controller (microcontroller) not shown here.

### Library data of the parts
C690 C691 C694-C698 = GRM21BF50J106ZE01L: CAP, CERM, 10 µF, 6.3 V, +80/-20%, Y5V, 0805; Manufacturer: MuRata; Polarized: N; CompType: Capacitor; Value: 10uF; U/M: EA; Cap_F: 0.00001; Tolerance_%: 80; ESR_ohm: 0.1; Value1: 0.1 ohm; VDC_V: 6.3; Value2: 6.3V; TaMin_C: -30; TaMax_C: 85; Cap_Case: 0805; SizeArea_mm2: 2.5; SizeAreaWB_mm2: 6.75; SizeX_mm: 2; SizeY_mm: 1.25; SizeZ_mm: 1.45; AEC Category: Q200
C692 C699 C701 C703 = GRM188R70J105KA01D: CAP, CERM, 1 µF, 6.3 V, +/- 10%, X7R, 0603; Manufacturer: MuRata; Polarized: N; CompType: Capacitor; Value: 1uF; U/M: EA; Cap_F: 0.000001; Tolerance_%: 10; Value1: Unknown; VDC_V: 6.3; Value2: 6.3V; TaMin_C: -55; TaMax_C: 125; SizeArea_mm2: 1.28; SizeAreaWB_mm2: 4.68; SizeX_mm: 1.6; SizeY_mm: 0.8; SizeZ_mm: 1; AEC Category: Q200
C693 C700 C702 C704 = GRM188R70J104KA01D: CAP, CERM, 0.1 µF, 6.3 V, +/- 10%, X7R, 0603; Manufacturer: MuRata; Polarized: N; CompType: Capacitor; Value: 0.1uF; U/M: EA; Cap_F: 0.0000001; Tolerance_%: 10; Value1: Unknown; VDC_V: 6.3; Value2: 6.3V; TaMin_C: -55; TaMax_C: 125; SizeArea_mm2: 1.28; SizeAreaWB_mm2: 4.68; SizeX_mm: 1.6; SizeY_mm: 0.8; SizeZ_mm: 1; AEC Category: Q200
C705 C708 = GRM32ER61E226KE15L: as C662-C665 on sheet system_power_03
C706 = GRM21BR61E475KA12L: CAP, CERM, 4.7 µF, 25 V, +/- 10%, X5R, 0805; Manufacturer: MuRata; Polarized: N; CompType: Capacitor; Value: 4.7uF; U/M: EA; Cap_F: 0.0000047; Tolerance_%: 10; ESR_ohm: 0.004; Value1: 0.004 ohm; VDC_V: 25; Value2: 25V; TaMin_C: -55; TaMax_C: 85; Cap_Case: 0805; SizeArea_mm2: 2.5; SizeAreaWB_mm2: 6.75; SizeX_mm: 2; SizeY_mm: 1.25; SizeZ_mm: 1.45; AEC Category: Q200
C707 = 08053C104KAT2A: as C660 on sheet system_power_03
C709 = CC0805KRX7R9BB272: CAP, CERM, 2700 pF, 50 V, +/- 10%, X7R, 0805; Manufacturer: Yageo America; Polarized: N; CompType: Capacitor; Value: 2700pF; U/M: EA; Cap_F: 0.0000000027; Tolerance_%: 10; Value1: Unknown; VDC_V: 50; Value2: 50V; TaMin_C: -55; TaMax_C: 125; Cap_Case: 0805; SizeArea_mm2: 2.5; SizeAreaWB_mm2: 6.75; SizeX_mm: 2; SizeY_mm: 1.25; SizeZ_mm: 1.45; AEC Category: Q200
C710 = GRM1555C1H271FA01D: CAP, CERM, 270 pF, 50 V, +/- 1%, C0G/NP0, 0402; Manufacturer: MuRata; Polarized: N; CompType: Capacitor; Value: 270pF; U/M: EA; Cap_F: 0.00000000027; Tolerance_%: 1; Value1: Unknown; VDC_V: 50; Value2: 50V; TaMin_C: -55; TaMax_C: 125; SizeArea_mm2: 0.5; SizeAreaWB_mm2: 3; SizeZ_mm: 0.6; AEC Category: Q200
C711 = GRM155C80J124KE01D: CAP, CERM, 0.12 µF, 6.3 V, +/- 10%, X6S, 0402; Manufacturer: MuRata; Polarized: N; CompType: Capacitor; Value: 0.12uF; U/M: EA; Cap_F: 0.00000012; Tolerance_%: 10; Value1: Unknown; VDC_V: 6.3; Value2: 6.3V; TaMin_C: -55; TaMax_C: 105; SizeArea_mm2: 0.5; SizeAreaWB_mm2: 3; SizeX_mm: 1; SizeZ_mm: 0.6; AEC Category: Q200
L46 = BLM18AG102SN1D: Ferrite Bead, 1000 ohm @ 100 MHz, 0.4 A, 0603; Manufacturer: MuRata; Imax_A: 0.4; DCR_ohm: 0.5; Value1: 0.5 ohm; Value2: 0.4A; ZTyp@100MHz_Ohm: 1000
L47 = SRN6045-6R8Y: as L45 on sheet system_power_03
R384 = CRCW04024K75FKED: as R366-R369 on sheet system_power_03
R385 = CRCW0402100RFKED: RES, 100, 1%, 0.063 W, 0402; Manufacturer: Vishay-Dale; CompType: Resistor; Value: 100; Value_Code: 100R; Tolerance_%: 1; Power_W: 0.063; Value2: 0.063W; VDC_V: 50; TempCo: 100 ppm/C; SizeArea_mm2: 0.5; SizeZ_mm: 0.6; EIA_Code: E96; U/M: EA; AEC Category: Q200
R386 = CRCW04021K00FKED: RES, 1.00 k, 1%, 0.063 W, 0402; Manufacturer: Vishay-Dale; CompType: Resistor; Value: 1.00k; Res_ohm: 1000; Value_Code: 1k00; Tolerance_%: 1; Power_W: 0.063; Value2: 0.063W; VDC_V: 50; TempCo: 100 ppm/C; EIA_Code: E96; U/M: EA
R387 = CRCW04020000Z0ED: as R358-R361 on sheet system_power_03
R388 R389 = CRCW04024K99FKED: RES, 4.99 k, 1%, 0.063 W, 0402; Manufacturer: Vishay-Dale; CompType: Resistor; Value: 4.99k; Res_ohm: 4990; Value_Code: 4k99; Tolerance_%: 1; Power_W: 0.063; Value2: 0.063W; VDC_V: 50; TempCo: 100 ppm/C; SizeArea_mm2: 0.5; SizeZ_mm: 0.6; EIA_Code: E96; U/M: EA; AEC Category: Q200
R390 = CRCW0402105KFKED: RES, 105 k, 1%, 0.063 W, 0402; Manufacturer: Vishay-Dale; CompType: Resistor; Value: 105k; Res_ohm: 105000; Tolerance_%: 1; Power_W: 0.063; Value2: 0.063W; VDC_V: 50; TempCo: 100 ppm/C; SizeArea_mm2: 0.5; SizeZ_mm: 0.6; EIA_Code: E96; U/M: EA; AEC Category: Q200
R391 = CRCW040230K9FKED: RES, 30.9 k, 1%, 0.063 W, 0402; Manufacturer: Vishay-Dale; CompType: Resistor; Value: 30.9k; Res_ohm: 30900; Value_Code: 30k9; Tolerance_%: 1; Power_W: 0.063; Value2: 0.063W; VDC_V: 50; TempCo: 100 ppm/C; SizeArea_mm2: 0.5; SizeZ_mm: 0.6; EIA_Code: E96; U/M: EA; AEC Category: Q200
R392 = CRCW040237K4FKED: RES, 37.4 k, 1%, 0.063 W, 0402; Manufacturer: Vishay-Dale; CompType: Resistor; Value: 37.4k; Res_ohm: 37400; Value_Code: 37k4; Tolerance_%: 1; Power_W: 0.063; Value2: 0.063W; VDC_V: 50; TempCo: 100 ppm/C; SizeArea_mm2: 0.5; SizeZ_mm: 0.6; EIA_Code: E96; U/M: EA; AEC Category: Q200
R393 R396 = CRCW040210K0DHEDP: RES, 10.0 k, 0.5%, 0.063 W, 0402; Manufacturer: Vishay-Dale; CompType: Resistor; Value: 10.0k; Res_ohm: 10000; Value_Code: 10k0; Tolerance_%: 0.5; Power_W: 0.063; Value2: 0.063W; VDC_V: 50; TempCo: 50 ppm/C; SizeX_mm: 1; SizeZ_mm: 0.6; EIA_Code: E192; U/M: EA; AEC Category: Q200
R394 = CRCW040253K6FKED: RES, 53.6 k, 1%, 0.063 W, 0402; Manufacturer: Vishay-Dale; CompType: Resistor; Value: 53.6k; Res_ohm: 53600; Value_Code: 53k6; Tolerance_%: 1; Power_W: 0.063; Value2: 0.063W; VDC_V: 50; TempCo: 100 ppm/C; SizeArea_mm2: 0.5; SizeZ_mm: 0.6; EIA_Code: E96; U/M: EA; AEC Category: Q200
R395 = CRCW0402845RFKED: RES, 845, 1%, 0.063 W, 0402; Manufacturer: Vishay-Dale; CompType: Resistor; Value: 845; Value_Code: 845R; Tolerance_%: 1; Power_W: 0.063; Value2: 0.063W; VDC_V: 50; TempCo: 100 ppm/C; SizeArea_mm2: 0.5; SizeZ_mm: 0.6; EIA_Code: E96; U/M: EA; AEC Category: Q200
U22 = TPS51200: IC REG SINK/SOURCE DDR 10-SON; Vendor Part Number: 296-23830-1-ND; Part Number: TPS51200DRCT; Manufacturer: TI; Check: CHKNOV19A; In Stock: NA; Cost @ 1K: 1.4; Cost @ 100: 2.205; Cost @ 10: 3.15; Vendor: Digikey
U23 = TPS54620RGYR: Buck Step Down Regulator with 4.5 to 17 V Input and 0.8 to 15 V Output, -40 to 150 degC, 14-Pin VQFN (RGY), Green (RoHS & no Sb/Br); Manufacturer: Texas Instruments; Alternate PartNumber: Equivalent; Duty Cycle(Max)(%): 98; Iout(Max)(A): 6; Iq(Typ)(mA): 0.6; Rating: Catalog; Regulated Outputs(#): 1; SubFamily: Step-Down Regulator; Switch Current Limit(Typ)(A): 8; Synchronous Rectification: TRUE; Vin(Max)(V): 17; Vin(Min)(V): 4.5; Vout(Max)(V): 15; Vout(Min)(V): 0.8

## Sheet system_power_05.SchDoc
size 431 x 279 mm; Date: Not shown in title block; ApprovedBy: Not shown in title block; CheckedBy: Not shown in title block; Author: Not shown in title block; CompanyName: Not shown in title block; Engineer: Not shown in title block; Organization: Not shown in title block; Address1: Not shown in title block; Address2: Not shown in title block; Address3: Not shown in title block; Address4: Not shown in title block; DocumentNumber: 38; Revision: Use project parameter SCH_Rev; SheetNumber: 38; SheetTotal: 38; PageSetup: Record=PageOptions¦CenterHorizontal=True¦CenterVertical=True¦PrintScale=1.00¦XCorrection=1.00¦YCorrection=1.00¦PrintKind=0¦BorderSize=5000000¦LeftOffset=0¦BottomOffset=0¦Orientation=2¦PaperLength=1000¦PaperWidth=1000¦Scale=100¦PaperSource=15¦PrintQuality=600¦MediaType=1¦DitherType=10¦PaperKind=Letter¦PrintScaleMode=1
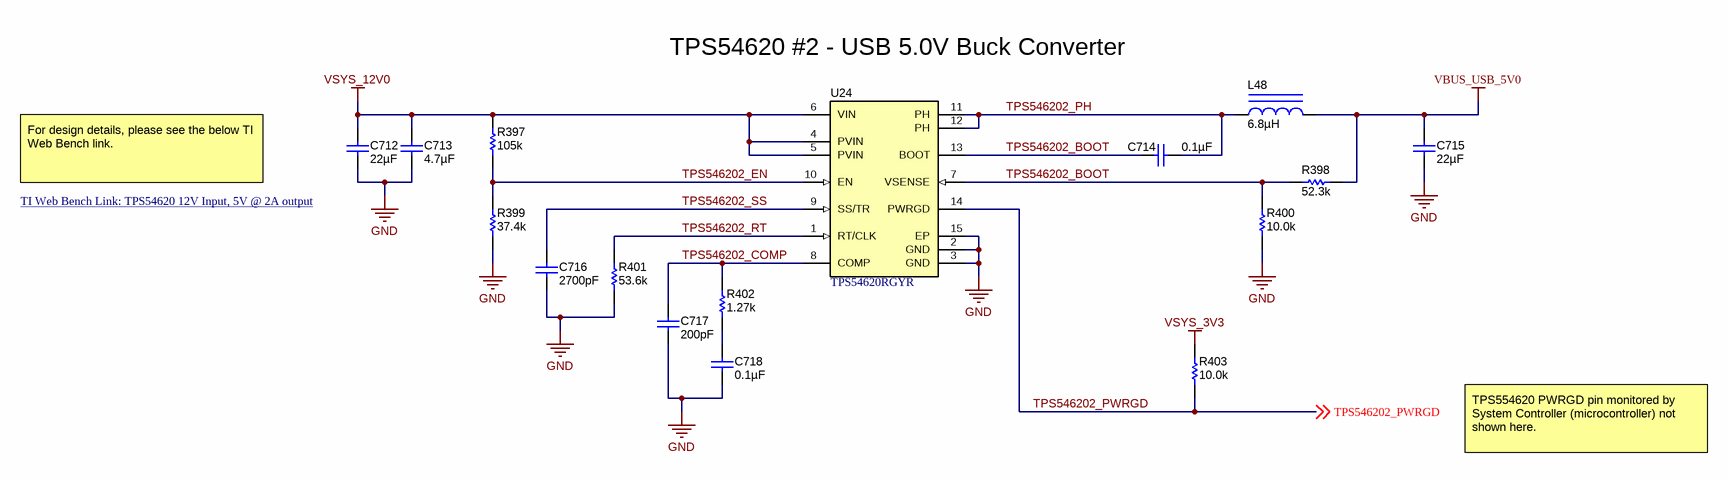
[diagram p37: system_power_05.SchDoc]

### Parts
C712  ValueDisplayed: 22µF  [1210_270]  (hidden comment: GRM32ER61E226KE15L)
C713  ValueDisplayed: 4.7µF  [0805_HV]  (hidden comment: GRM21BR61E475KA12L)
C714  ValueDisplayed: 0.1µF  [0805_HV]  (hidden comment: 08053C104KAT2A)
C715  ValueDisplayed: 22µF  [1210_270]  (hidden comment: GRM32ER61E226KE15L)
C716  ValueDisplayed: 2700pF  [0805_HV]  (hidden comment: CC0805KRX7R9BB272)
C717  ValueDisplayed: 200pF  [0402]  (hidden comment: GRM1555C1H201JA01D)
C718  ValueDisplayed: 0.1µF  [0805_HV]  (hidden comment: GRM21BR71E104KA01L)
L48  ValueDisplayed: 6.8µH  [SRN6045]  (hidden comment: SRN6045-6R8Y)
R397  ValueDisplayed: 105k  [0402]  (hidden comment: CRCW0402105KFKED)
R398  ValueDisplayed: 52.3k  [0402]  (hidden comment: CRCW040252K3FKED)
R399  ValueDisplayed: 37.4k  [0402]  (hidden comment: CRCW040237K4FKED)
R400  ValueDisplayed: 10.0k  [0402]  (hidden comment: CRCW040210K0DHEDP)
R401  ValueDisplayed: 53.6k  [0402]  (hidden comment: CRCW040253K6FKED)
R402  ValueDisplayed: 1.27k  [0402]  (hidden comment: CRCW04021K27FKED)
R403  ValueDisplayed: 10.0k  [0402]  (hidden comment: CRCW040210K0DHEDP)
U24  TPS54620RGYR  [RHL0014A]

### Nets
GND: C712.2 C713.2 C715.2 C716.2 C717.2 C718.2 R399.1 R400.1 R401.1 U24.2(GND) U24.3(GND) U24.15(EP)  [project net DAC_OUT0N_T1]
VBUS_USB_5V0: C715.1 L48.2 R398.2
VSYS_3V3: R403.2
VSYS_12V0: C712.1 C713.1 R397.2 U24.4(PVIN) U24.5(PVIN) U24.6(VIN)
TPS546202_BOOT: C714.2 R398.1 R400.2 U24.7(VSENSE) U24.13(BOOT)
TPS546202_COMP: C717.1 R402.2 U24.8(COMP)
TPS546202_EN: R397.1 R399.2 U24.10(EN)
TPS546202_PH: C714.1 L48.1 U24.11(PH) U24.12(PH)
TPS546202_PWRGD: R403.1 U24.14(PWRGD) ; off-sheet TPS546202_PWRGD
TPS546202_RT: R401.2 U24.1(RT/CLK)
TPS546202_SS: C716.1 U24.9(SS/TR)
NetC718_1: C718.1 R402.1

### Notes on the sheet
- TPS54620 #2 - USB 5.0V Buck Converter
- For design details, please see the below TI Web Bench link.
- (near C712) TI Web Bench Link: TPS54620 12V Input, 5V @ 2A output <https://webench.ti.com/appinfo/webench/scripts/SDP.cgi?ID=9C7178BC14FEBCDB>
- TPS554620 PWRGD pin monitored by System Controller (microcontroller) not shown here.

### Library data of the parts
C712 C715 = GRM32ER61E226KE15L: as C662-C665 on sheet system_power_03
C713 = GRM21BR61E475KA12L: as C706 on sheet system_power_04
C714 = 08053C104KAT2A: as C660 on sheet system_power_03
C716 = CC0805KRX7R9BB272: as C709 on sheet system_power_04
C717 = GRM1555C1H201JA01D: CAP, CERM, 200 pF, 50 V, +/- 5%, C0G/NP0, 0402; Manufacturer: MuRata; Polarized: N; CompType: Capacitor; Value: 200pF; U/M: EA; Cap_F: 0.0000000002; Tolerance_%: 5; Value1: Unknown; VDC_V: 50; Value2: 50V; TaMin_C: -55; TaMax_C: 125; SizeArea_mm2: 0.5; SizeAreaWB_mm2: 3; SizeX_mm: 1; SizeZ_mm: 0.6; AEC Category: Q200
C718 = GRM21BR71E104KA01L: CAP, CERM, 0.1 µF, 25 V, +/- 10%, X7R, 0805; Manufacturer: MuRata; Polarized: N; CompType: Capacitor; Value: 0.1uF; U/M: EA; Cap_F: 0.0000001; Tolerance_%: 10; Value1: Unknown; VDC_V: 25; Value2: 25V; TaMin_C: -55; TaMax_C: 125; Cap_Case: 0805; SizeArea_mm2: 2.5; SizeAreaWB_mm2: 6.75; SizeX_mm: 2; SizeY_mm: 1.25; SizeZ_mm: 1.45; AEC Category: Q200
L48 = SRN6045-6R8Y: as L45 on sheet system_power_03
R397 = CRCW0402105KFKED: as R390 on sheet system_power_04
R398 = CRCW040252K3FKED: RES, 52.3 k, 1%, 0.063 W, 0402; Manufacturer: Vishay-Dale; CompType: Resistor; Value: 52.3k; Res_ohm: 52300; Value_Code: 52k3; Tolerance_%: 1; Power_W: 0.063; Value2: 0.063W; VDC_V: 50; TempCo: 100 ppm/C; SizeArea_mm2: 0.5; SizeZ_mm: 0.6; EIA_Code: E96; U/M: EA; AEC Category: Q200
R399 = CRCW040237K4FKED: as R392 on sheet system_power_04
R400 R403 = CRCW040210K0DHEDP: as R393 on sheet system_power_04
R401 = CRCW040253K6FKED: as R394 on sheet system_power_04
R402 = CRCW04021K27FKED: RES, 1.27 k, 1%, 0.063 W, 0402; Manufacturer: Vishay-Dale; CompType: Resistor; Value: 1.27k; Res_ohm: 1270; Value_Code: 1k27; Tolerance_%: 1; Power_W: 0.063; Value2: 0.063W; VDC_V: 50; TempCo: 100 ppm/C; SizeArea_mm2: 0.5; SizeZ_mm: 0.6; EIA_Code: E96; U/M: EA; AEC Category: Q200
U24 = TPS54620RGYR: as U23 on sheet system_power_04

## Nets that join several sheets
DAC_OUT0N_T1: k2l_soc_01 (266 pins), k2l_soc_02 (117 pins), k2l_soc_03 (126 pins), k2l_soc_03_1 (43 pins), k2l_soc_04 (32 pins), k2l_soc_05 (9 pins), k2l_soc_06 (22 pins), k2l_soc_07 (11 pins), k2l_soc_08 (R23.1 R24.1), k2l_soc_09 (C333.2 R140.1 R141.1 R142.1), k2l_soc_09_2 (66 pins), k2l_soc_09_3 (66 pins), k2l_soc_09_4 (33 pins), k2l_soc_10 (19 pins), k2l_soc_13 (10 pins), k2l_soc_14 (R181.1 R182.1), adc32rf4x_01 (40 pins), adc32rf4x_02 (20 pins), dac38j84_01 (121 pins), dac38j84_02 (8 pins), dac38j84_03 (46 pins), dac38j84_04 (46 pins), lmk04828_01 (31 pins), lmk04828_02 (18 pins), cdcm6208_1 (47 pins), system_power_01 (41 pins), system_power_02 (40 pins), system_power_03 (40 pins), system_power_04 (28 pins), system_power_05 (12 pins)
LMK_VCC1: lmk04828_01 (C542.1 L20.2), lmk04828_02 (U15.10)
LMK_VCC2: lmk04828_01 (C544.1 L21.2), lmk04828_02 (U15.17)
LMK_VCC3: lmk04828_01 (C546.1 L22.2), lmk04828_02 (U15.21)
LMK_VCC4: lmk04828_01 (C548.1 L23.2), lmk04828_02 (U15.26)
LMK_VCC5: lmk04828_01 (C550.1 L24.2), lmk04828_02 (U15.33)
LMK_VCC6: lmk04828_01 (C552.1 L25.2), lmk04828_02 (U15.36)
LMK_VCC7: lmk04828_01 (C554.1 L26.2), lmk04828_02 (U15.39)
LMK_VCC8: lmk04828_01 (C556.1 L27.2), lmk04828_02 (U15.42)
LMK_VCC9: lmk04828_01 (C558.1 L28.2), lmk04828_02 (U15.45)
LMK_VCC10: lmk04828_01 (C560.1 L29.2), lmk04828_02 (U15.47)
LMK_VCC11: lmk04828_01 (C562.1 L30.2), lmk04828_02 (U15.53)
LMK_VCC12: lmk04828_01 (C564.1 L31.2), lmk04828_02 (U15.64)
VBUS_USB_5V0: k2l_soc_10 (7 pins), system_power_05 (C715.1 L48.2 R398.2)
VK2L_0V85: k2l_soc_04 (14 pins), k2l_soc_10 (R148.2 R149.2), system_power_02 (C646.1 L40.2 R348.2)
VK2L_CVDD1V0: k2l_soc_03 (37 pins), system_power_02 (C651.1 L41.2 R351.2)
VK2L_DDR_1V35: k2l_soc_03 (90 pins), k2l_soc_09 (C332.1), k2l_soc_09_2 (54 pins), k2l_soc_09_3 (54 pins), k2l_soc_09_4 (27 pins), system_power_03 (C668.1 L42.3 R362.2), system_power_04 (5 pins)
VK2L_DDR_VREF: k2l_soc_09 (C333.1 U1.F15), k2l_soc_09_2 (8 pins), k2l_soc_09_3 (8 pins), k2l_soc_09_4 (C378.1 C379.1 U7.H1 U7.M8), system_power_04 (C701.1 C702.1 U22.6)
VK2L_DDR_VTT: k2l_soc_09 (26 pins), system_power_04 (7 pins)
VSYS_1V8: k2l_soc_02 (6 pins), k2l_soc_03 (110 pins), k2l_soc_03_1 (25 pins), k2l_soc_05 (R1.2 R2.2 R3.2 R13.2), k2l_soc_06 (22 pins), k2l_soc_06_1 (R15.2 R16.2), k2l_soc_07 (6 pins), k2l_soc_10 (U11.5), k2l_soc_13 (11 pins), cdcm6208_1 (C577.1 L33.1 R290.2), system_power_02 (C640.1 L39.2 R343.2)
VSYS_3V3: k2l_soc_04 (7 pins), cdcm6208_1 (6 pins), system_power_01 (R302.2 R303.2 U18.7), system_power_02 (C638.1 L38.2 R336.1), system_power_04 (C690.1 L46.1 R384.2 R396.2), system_power_05 (R403.2)
VSYS_12V0: system_power_01 (15 pins), system_power_02 (12 pins), system_power_03 (12 pins), system_power_04 (6 pins), system_power_05 (6 pins)
VSYS_DVDD1V8: adc32rf4x_01 (R183.2), dac38j84_01 (28 pins), lmk04828_02 (C571.1 U16.4)
VSYS_DVDD3V3: dac38j84_01 (C516.1 C517.1 C518.1 L19.2), lmk04828_01 (31 pins), lmk04828_02 (R274.2), system_power_01 (R313.2 R314.2 R315.2 R316.2)
ADC_AINM: adc32rf4x_02 (C434.1 T2.2), adc32rf4x_03 (U13.41)
ADC_AINP: adc32rf4x_02 (C430.1 T2.1), adc32rf4x_03 (U13.42)
ADC_BINM: adc32rf4x_02 (C440.1 T4.2), adc32rf4x_03 (U13.14)
ADC_BINP: adc32rf4x_02 (C436.1 T4.1), adc32rf4x_03 (U13.13)
ADC_DEVCLKN: adc32rf4x_03 (C443.2), lmk04828_02 (U15.2)
ADC_DEVCLKP: adc32rf4x_03 (C442.2), lmk04828_02 (U15.1)
DAC_DACCLKN: dac38j84_02 (C522.2), lmk04828_02 (R278.2 U15.14)
DAC_DACCLKP: dac38j84_02 (C520.2), lmk04828_02 (R279.2 U15.13)
DAC_OUT0N: dac38j84_02 (U14.C12), dac38j84_03 (R216.1 R217.1 R218.1 R222.2)
DAC_OUT0P: dac38j84_02 (U14.B12), dac38j84_03 (R209.2 R210.2 R211.2 R212.2)
DAC_OUT1N: dac38j84_02 (U14.D12), dac38j84_03 (R232.1 R233.1 R234.1 R238.2)
DAC_OUT1P: dac38j84_02 (U14.E12), dac38j84_03 (R225.2 R226.2 R227.2 R228.2)
DAC_OUT2N: dac38j84_02 (U14.J12), dac38j84_04 (R248.1 R249.1 R250.1 R254.2)
DAC_OUT2P: dac38j84_02 (U14.H12), dac38j84_04 (R241.2 R242.2 R243.2 R244.2)
DAC_OUT3N: dac38j84_02 (U14.K12), dac38j84_04 (R264.1 R265.1 R266.1 R270.2)
DAC_OUT3P: dac38j84_02 (U14.L12), dac38j84_04 (R257.2 R258.2 R259.2 R260.2)
DAC_SYNCBN: k2l_soc_08 (K11.1 U1.AG13), dac38j84_02 (U14.B6)
DAC_SYNCBP: k2l_soc_08 (K9.1 U1.AG12), dac38j84_02 (U14.B7)
DAC_SYSREFN: dac38j84_02 (C524.2), lmk04828_02 (R280.2 U15.16)
DAC_SYSREFP: dac38j84_02 (C523.2), lmk04828_02 (R281.2 U15.15)
K2L_ADC_SPI0CLK: k2l_soc_06_1 (R17.1), adc32rf4x_01 (R192.2)
K2L_ADC_SPI0SCS0: k2l_soc_06_1 (R19.1), adc32rf4x_01 (R193.2)
K2L_ADC_SPI0SIMO: k2l_soc_06_1 (R18.1), adc32rf4x_01 (R194.2)
K2L_ADC_SPI0SOMI: k2l_soc_06_1 (U1.N27), adc32rf4x_01 (R195.2)
K2L_CORESEL0_BOOTMODE13: k2l_soc_05 (U1.AE5), k2l_soc_06 (R31.1 R45.2)
K2L_DAC_SPI1CLK: k2l_soc_06_1 (R20.1), dac38j84_02 (K34.1 U14.L9)
K2L_DAC_SPI1SCS0: k2l_soc_06_1 (R22.1), dac38j84_02 (K32.1 U14.M9)
K2L_DAC_SPI1SIMO: k2l_soc_06_1 (R21.1), dac38j84_02 (K30.1 U14.L10)
K2L_DAC_SPI1SOMI: k2l_soc_06_1 (U1.L26), dac38j84_02 (R205.1)
K2L_DDR3A0: k2l_soc_09 (R114.1 U1.C14), k2l_soc_09_2 (U3.N3 U4.N3), k2l_soc_09_3 (U5.N3 U6.N3), k2l_soc_09_4 (U7.N3)
K2L_DDR3A1: k2l_soc_09 (R115.1 U1.D14), k2l_soc_09_2 (U3.P7 U4.P7), k2l_soc_09_3 (U5.P7 U6.P7), k2l_soc_09_4 (U7.P7)
K2L_DDR3A2: k2l_soc_09 (R116.1 U1.A18), k2l_soc_09_2 (U3.P3 U4.P3), k2l_soc_09_3 (U5.P3 U6.P3), k2l_soc_09_4 (U7.P3)
K2L_DDR3A3: k2l_soc_09 (R117.1 U1.E14), k2l_soc_09_2 (U3.N2 U4.N2), k2l_soc_09_3 (U5.N2 U6.N2), k2l_soc_09_4 (U7.N2)
K2L_DDR3A4: k2l_soc_09 (R118.1 U1.C15), k2l_soc_09_2 (U3.P8 U4.P8), k2l_soc_09_3 (U5.P8 U6.P8), k2l_soc_09_4 (U7.P8)
K2L_DDR3A5: k2l_soc_09 (R119.1 U1.A17), k2l_soc_09_2 (U3.P2 U4.P2), k2l_soc_09_3 (U5.P2 U6.P2), k2l_soc_09_4 (U7.P2)
K2L_DDR3A6: k2l_soc_09 (R120.1 U1.D15), k2l_soc_09_2 (U3.R8 U4.R8), k2l_soc_09_3 (U5.R8 U6.R8), k2l_soc_09_4 (U7.R8)
K2L_DDR3A7: k2l_soc_09 (R121.1 U1.B16), k2l_soc_09_2 (U3.R2 U4.R2), k2l_soc_09_3 (U5.R2 U6.R2), k2l_soc_09_4 (U7.R2)
K2L_DDR3A8: k2l_soc_09 (R122.1 U1.B17), k2l_soc_09_2 (U3.T8 U4.T8), k2l_soc_09_3 (U5.T8 U6.T8), k2l_soc_09_4 (U7.T8)
K2L_DDR3A9: k2l_soc_09 (R123.1 U1.D17), k2l_soc_09_2 (U3.R3 U4.R3), k2l_soc_09_3 (U5.R3 U6.R3), k2l_soc_09_4 (U7.R3)
K2L_DDR3A10: k2l_soc_09 (R124.1 U1.B12), k2l_soc_09_2 (U3.L7 U4.L7), k2l_soc_09_3 (U5.L7 U6.L7), k2l_soc_09_4 (U7.L7)
K2L_DDR3A11: k2l_soc_09 (R125.1 U1.B18), k2l_soc_09_2 (U3.R7 U4.R7), k2l_soc_09_3 (U5.R7 U6.R7), k2l_soc_09_4 (U7.R7)
K2L_DDR3A12: k2l_soc_09 (R126.1 U1.C17), k2l_soc_09_2 (U3.N7 U4.N7), k2l_soc_09_3 (U5.N7 U6.N7), k2l_soc_09_4 (U7.N7)
K2L_DDR3A13: k2l_soc_09 (R127.1 U1.B11), k2l_soc_09_2 (U3.T3 U4.T3), k2l_soc_09_3 (U5.T3 U6.T3), k2l_soc_09_4 (U7.T3)
K2L_DDR3A14: k2l_soc_09 (R128.1 U1.E18), k2l_soc_09_2 (U3.T7 U4.T7), k2l_soc_09_3 (U5.T7 U6.T7), k2l_soc_09_4 (U7.T7)
K2L_DDR3ACLKN: k2l_soc_05 (C3.1 C3.2 U1.G30), k2l_soc_10 (C390.2), cdcm6208_1 (U17.15 U17.21)
K2L_DDR3ACLKP: k2l_soc_05 (C4.1 C4.2 U1.F30), k2l_soc_10 (C389.2), cdcm6208_1 (U17.14 U17.20)
K2L_DDR3BA0: k2l_soc_09 (R133.1 U1.E11), k2l_soc_09_2 (U3.M2 U4.M2), k2l_soc_09_3 (U5.M2 U6.M2), k2l_soc_09_4 (U7.M2)
K2L_DDR3BA1: k2l_soc_09 (R132.1 U1.F12), k2l_soc_09_2 (U3.N8 U4.N8), k2l_soc_09_3 (U5.N8 U6.N8), k2l_soc_09_4 (U7.N8)
K2L_DDR3BA2: k2l_soc_09 (R131.1 U1.E12), k2l_soc_09_2 (U3.M3 U4.M3), k2l_soc_09_3 (U5.M3 U6.M3), k2l_soc_09_4 (U7.M3)
K2L_DDR3CASZ: k2l_soc_09 (R136.1 U1.A13), k2l_soc_09_2 (U3.K3 U4.K3), k2l_soc_09_3 (U5.K3 U6.K3), k2l_soc_09_4 (U7.K3)
K2L_DDR3CB0: k2l_soc_09_1 (U1.F19), k2l_soc_09_4 (U7.E3)
K2L_DDR3CB1: k2l_soc_09_1 (U1.F20), k2l_soc_09_4 (U7.F7)
K2L_DDR3CB2: k2l_soc_09_1 (U1.F18), k2l_soc_09_4 (U7.F2)
K2L_DDR3CB3: k2l_soc_09_1 (U1.E20), k2l_soc_09_4 (U7.F8)
K2L_DDR3CB4: k2l_soc_09_1 (U1.E19), k2l_soc_09_4 (U7.H3)
K2L_DDR3CB5: k2l_soc_09_1 (U1.D19), k2l_soc_09_4 (U7.H8)
K2L_DDR3CB6: k2l_soc_09_1 (U1.C19), k2l_soc_09_4 (U7.G2)
K2L_DDR3CB7: k2l_soc_09_1 (U1.B19), k2l_soc_09_4 (U7.H7)
K2L_DDR3CE0: k2l_soc_09 (R138.1 U1.A14), k2l_soc_09_2 (U3.L2 U4.L2), k2l_soc_09_3 (U5.L2 U6.L2), k2l_soc_09_4 (U7.L2)
K2L_DDR3CKE0: k2l_soc_09 (R137.1 U1.E17), k2l_soc_09_2 (U3.K9 U4.K9), k2l_soc_09_3 (U5.K9 U6.K9), k2l_soc_09_4 (U7.K9)
K2L_DDR3CLKOUTN0: k2l_soc_09 (R113.1 U1.A15), k2l_soc_09_2 (U3.K7 U4.K7), k2l_soc_09_3 (U5.K7 U6.K7), k2l_soc_09_4 (U7.K7)
K2L_DDR3CLKOUTP0: k2l_soc_09 (R112.1 U1.A16), k2l_soc_09_2 (U3.J7 U4.J7), k2l_soc_09_3 (U5.J7 U6.J7), k2l_soc_09_4 (U7.J7)
K2L_DDR3D0: k2l_soc_09_1 (U1.E1), k2l_soc_09_2 (U3.E3)
K2L_DDR3D1: k2l_soc_09_1 (U1.C2), k2l_soc_09_2 (U3.F7)
K2L_DDR3D2: k2l_soc_09_1 (U1.B2), k2l_soc_09_2 (U3.F2)
K2L_DDR3D3: k2l_soc_09_1 (U1.C1), k2l_soc_09_2 (U3.F8)
K2L_DDR3D4: k2l_soc_09_1 (U1.D1), k2l_soc_09_2 (U3.H3)
K2L_DDR3D5: k2l_soc_09_1 (U1.D2), k2l_soc_09_2 (U3.H8)
K2L_DDR3D6: k2l_soc_09_1 (U1.E2), k2l_soc_09_2 (U3.G2)
K2L_DDR3D7: k2l_soc_09_1 (U1.E3), k2l_soc_09_2 (U3.H7)
K2L_DDR3D8: k2l_soc_09_1 (U1.A5), k2l_soc_09_2 (U3.D7)
K2L_DDR3D9: k2l_soc_09_1 (U1.D6), k2l_soc_09_2 (U3.C3)
K2L_DDR3D10: k2l_soc_09_1 (U1.E6), k2l_soc_09_2 (U3.C8)
K2L_DDR3D11: k2l_soc_09_1 (U1.B5), k2l_soc_09_2 (U3.C2)
K2L_DDR3D12: k2l_soc_09_1 (U1.F6), k2l_soc_09_2 (U3.A7)
K2L_DDR3D13: k2l_soc_09_1 (U1.D4), k2l_soc_09_2 (U3.A2)
K2L_DDR3D14: k2l_soc_09_1 (U1.C4), k2l_soc_09_2 (U3.B8)
K2L_DDR3D15: k2l_soc_09_1 (U1.F5), k2l_soc_09_2 (U3.A3)
K2L_DDR3D16: k2l_soc_09_1 (U1.F8), k2l_soc_09_2 (U4.E3)
K2L_DDR3D17: k2l_soc_09_1 (U1.E7), k2l_soc_09_2 (U4.F7)
K2L_DDR3D18: k2l_soc_09_1 (U1.C6), k2l_soc_09_2 (U4.F2)
K2L_DDR3D19: k2l_soc_09_1 (U1.B6), k2l_soc_09_2 (U4.F8)
K2L_DDR3D20: k2l_soc_09_1 (U1.F7), k2l_soc_09_2 (U4.H3)
K2L_DDR3D21: k2l_soc_09_1 (U1.E8), k2l_soc_09_2 (U4.H8)
K2L_DDR3D22: k2l_soc_09_1 (U1.D8), k2l_soc_09_2 (U4.G2)
K2L_DDR3D23: k2l_soc_09_1 (U1.C8), k2l_soc_09_2 (U4.H7)
K2L_DDR3D24: k2l_soc_09_1 (U1.F10), k2l_soc_09_2 (U4.D7)
K2L_DDR3D25: k2l_soc_09_1 (U1.D10), k2l_soc_09_2 (U4.C3)
K2L_DDR3D26: k2l_soc_09_1 (U1.E10), k2l_soc_09_2 (U4.C8)
K2L_DDR3D27: k2l_soc_09_1 (U1.C10), k2l_soc_09_2 (U4.C2)
K2L_DDR3D28: k2l_soc_09_1 (U1.A9), k2l_soc_09_2 (U4.A7)
K2L_DDR3D29: k2l_soc_09_1 (U1.A8), k2l_soc_09_2 (U4.A2)
K2L_DDR3D30: k2l_soc_09_1 (U1.B9), k2l_soc_09_2 (U4.B8)
K2L_DDR3D31: k2l_soc_09_1 (U1.E9), k2l_soc_09_2 (U4.A3)
K2L_DDR3D32: k2l_soc_09_1 (U1.A21), k2l_soc_09_3 (U5.A3)
K2L_DDR3D33: k2l_soc_09_1 (U1.B21), k2l_soc_09_3 (U5.B8)
K2L_DDR3D34: k2l_soc_09_1 (U1.C21), k2l_soc_09_3 (U5.A2)
K2L_DDR3D35: k2l_soc_09_1 (U1.D21), k2l_soc_09_3 (U5.A7)
K2L_DDR3D36: k2l_soc_09_1 (U1.E22), k2l_soc_09_3 (U5.C2)
K2L_DDR3D37: k2l_soc_09_1 (U1.E21), k2l_soc_09_3 (U5.C8)
K2L_DDR3D38: k2l_soc_09_1 (U1.E23), k2l_soc_09_3 (U5.C3)
K2L_DDR3D39: k2l_soc_09_1 (U1.F23), k2l_soc_09_3 (U5.D7)
K2L_DDR3D40: k2l_soc_09_1 (U1.F25), k2l_soc_09_3 (U5.H7)
K2L_DDR3D41: k2l_soc_09_1 (U1.D25), k2l_soc_09_3 (U5.G2)
K2L_DDR3D42: k2l_soc_09_1 (U1.C23), k2l_soc_09_3 (U5.H8)
K2L_DDR3D43: k2l_soc_09_1 (U1.E25), k2l_soc_09_3 (U5.H3)
K2L_DDR3D44: k2l_soc_09_1 (U1.E24), k2l_soc_09_3 (U5.F8)
K2L_DDR3D45: k2l_soc_09_1 (U1.D23), k2l_soc_09_3 (U5.F2)
K2L_DDR3D46: k2l_soc_09_1 (U1.F24), k2l_soc_09_3 (U5.F7)
K2L_DDR3D47: k2l_soc_09_1 (U1.B23), k2l_soc_09_3 (U5.E3)
K2L_DDR3D48: k2l_soc_09_1 (U1.C25), k2l_soc_09_3 (U6.E3)
K2L_DDR3D49: k2l_soc_09_1 (U1.B25), k2l_soc_09_3 (U6.F7)
K2L_DDR3D50: k2l_soc_09_1 (U1.A25), k2l_soc_09_3 (U6.F2)
K2L_DDR3D51: k2l_soc_09_1 (U1.A27), k2l_soc_09_3 (U6.F8)
K2L_DDR3D52: k2l_soc_09_1 (U1.E26), k2l_soc_09_3 (U6.H3)
K2L_DDR3D53: k2l_soc_09_1 (U1.E27), k2l_soc_09_3 (U6.H8)
K2L_DDR3D54: k2l_soc_09_1 (U1.D27), k2l_soc_09_3 (U6.G2)
K2L_DDR3D55: k2l_soc_09_1 (U1.B27), k2l_soc_09_3 (U6.H7)
K2L_DDR3D56: k2l_soc_09_1 (U1.E30), k2l_soc_09_3 (U6.D7)
K2L_DDR3D57: k2l_soc_09_1 (U1.E29), k2l_soc_09_3 (U6.C3)
K2L_DDR3D58: k2l_soc_09_1 (U1.F29), k2l_soc_09_3 (U6.C8)
K2L_DDR3D59: k2l_soc_09_1 (U1.D30), k2l_soc_09_3 (U6.C2)
K2L_DDR3D60: k2l_soc_09_1 (U1.C30), k2l_soc_09_3 (U6.A7)
K2L_DDR3D61: k2l_soc_09_1 (U1.D29), k2l_soc_09_3 (U6.A2)
K2L_DDR3D62: k2l_soc_09_1 (U1.B28), k2l_soc_09_3 (U6.B8)
K2L_DDR3D63: k2l_soc_09_1 (U1.A28), k2l_soc_09_3 (U6.A3)
K2L_DDR3DQM0: k2l_soc_09_1 (U1.E4), k2l_soc_09_2 (U3.E7)
K2L_DDR3DQM1: k2l_soc_09_1 (U1.E5), k2l_soc_09_2 (U3.D3)
K2L_DDR3DQM2: k2l_soc_09_1 (U1.A6), k2l_soc_09_2 (U4.E7)
K2L_DDR3DQM3: k2l_soc_09_1 (U1.B8), k2l_soc_09_2 (U4.D3)
K2L_DDR3DQM4: k2l_soc_09_1 (U1.F22), k2l_soc_09_3 (U5.E7)
K2L_DDR3DQM5: k2l_soc_09_1 (U1.A23), k2l_soc_09_3 (U5.D3)
K2L_DDR3DQM6: k2l_soc_09_1 (U1.C27), k2l_soc_09_3 (U6.E7)
K2L_DDR3DQM7: k2l_soc_09_1 (U1.E28), k2l_soc_09_3 (U6.D3)
K2L_DDR3DQM8: k2l_soc_09_1 (U1.A19), k2l_soc_09_4 (U7.E7)
K2L_DDR3DQSN0: k2l_soc_09_1 (U1.B3), k2l_soc_09_2 (U3.G3)
K2L_DDR3DQSN1: k2l_soc_09_1 (U1.A4), k2l_soc_09_2 (U3.B7)
K2L_DDR3DQSN2: k2l_soc_09_1 (U1.B7), k2l_soc_09_2 (U4.G3)
K2L_DDR3DQSN3: k2l_soc_09_1 (U1.B10), k2l_soc_09_2 (U4.B7)
K2L_DDR3DQSN4: k2l_soc_09_1 (U1.B22), k2l_soc_09_3 (U5.G3)
K2L_DDR3DQSN5: k2l_soc_09_1 (U1.A24), k2l_soc_09_3 (U5.B7)
K2L_DDR3DQSN6: k2l_soc_09_1 (U1.A26), k2l_soc_09_3 (U6.G3)
K2L_DDR3DQSN7: k2l_soc_09_1 (U1.B29), k2l_soc_09_3 (U6.B7)
K2L_DDR3DQSN8: k2l_soc_09_1 (U1.B20), k2l_soc_09_4 (U7.G3)
K2L_DDR3DQSP0: k2l_soc_09_1 (U1.A3), k2l_soc_09_2 (U3.F3)
K2L_DDR3DQSP1: k2l_soc_09_1 (U1.B4), k2l_soc_09_2 (U3.C7)
K2L_DDR3DQSP2: k2l_soc_09_1 (U1.A7), k2l_soc_09_2 (U4.F3)
K2L_DDR3DQSP3: k2l_soc_09_1 (U1.A10), k2l_soc_09_2 (U4.C7)
K2L_DDR3DQSP4: k2l_soc_09_1 (U1.A22), k2l_soc_09_3 (U5.F3)
K2L_DDR3DQSP5: k2l_soc_09_1 (U1.B24), k2l_soc_09_3 (U5.C7)
K2L_DDR3DQSP6: k2l_soc_09_1 (U1.B26), k2l_soc_09_3 (U6.F3)
K2L_DDR3DQSP7: k2l_soc_09_1 (U1.C29), k2l_soc_09_3 (U6.C7)
K2L_DDR3DQSP8: k2l_soc_09_1 (U1.A20), k2l_soc_09_4 (U7.F3)
K2L_DDR3ODT0: k2l_soc_09 (R139.1 U1.A12), k2l_soc_09_2 (U3.K1 U4.K1), k2l_soc_09_3 (U5.K1 U6.K1), k2l_soc_09_4 (U7.K1)
K2L_DDR3RASZ: k2l_soc_09 (R135.1 U1.B13), k2l_soc_09_2 (U3.J3 U4.J3), k2l_soc_09_3 (U5.J3 U6.J3), k2l_soc_09_4 (U7.J3)
K2L_DDR3RESETZ: k2l_soc_09 (R130.1 U1.E15), k2l_soc_09_2 (U3.T2 U4.T2), k2l_soc_09_3 (U5.T2 U6.T2), k2l_soc_09_4 (U7.T2)
K2L_DDR3WEZ: k2l_soc_09 (R134.1 U1.D12), k2l_soc_09_2 (U3.L3 U4.L3), k2l_soc_09_3 (U5.L3 U6.L3), k2l_soc_09_4 (U7.L3)
K2L_DFEIO2: k2l_soc_08 (U1.AG7), adc32rf4x_01 (R186.2)
K2L_DFEIO3: k2l_soc_08 (U1.AK5), adc32rf4x_01 (R187.2)
K2L_DFEIO4: k2l_soc_08 (U1.AH7), adc32rf4x_01 (R188.2)
K2L_DFEIO5: k2l_soc_08 (U1.AK6), adc32rf4x_01 (R189.2)
K2L_DFEIO6: k2l_soc_08 (U1.AJ7), adc32rf4x_01 (R190.2)
K2L_DFEIO7: k2l_soc_08 (U1.AG8), adc32rf4x_01 (R191.2)
K2L_DFESYNCOUT_N0: k2l_soc_08 (U1.AJ10), adc32rf4x_03 (K25.1 U13.36)
K2L_DFESYNCOUT_P0: k2l_soc_08 (U1.AJ9), adc32rf4x_03 (K24.1 U13.35)
K2L_DFESYSREFN: k2l_soc_08 (K8.1 U1.AF30), lmk04828_02 (U15.23)
K2L_DFESYSREFP: k2l_soc_08 (K7.1 U1.AE30), lmk04828_02 (U15.22)
K2L_JESD_RXN0: k2l_soc_08 (C6.2), adc32rf4x_03 (U13.65)
K2L_JESD_RXN1: k2l_soc_08 (C8.2), adc32rf4x_03 (U13.68)
K2L_JESD_RXN2: k2l_soc_08 (C10.2), adc32rf4x_03 (U13.71)
K2L_JESD_RXN3: k2l_soc_08 (C12.2), adc32rf4x_03 (U13.1)
K2L_JESD_RXP0: k2l_soc_08 (C5.2), adc32rf4x_03 (U13.66)
K2L_JESD_RXP1: k2l_soc_08 (C7.2), adc32rf4x_03 (U13.69)
K2L_JESD_RXP2: k2l_soc_08 (C9.2), adc32rf4x_03 (U13.72)
K2L_JESD_RXP3: k2l_soc_08 (C11.2), adc32rf4x_03 (U13.2)
K2L_JESD_SERDES0_REFCLKN: k2l_soc_08 (K4.1 U1.AF18), lmk04828_02 (U15.28)
K2L_JESD_SERDES0_REFCLKP: k2l_soc_08 (K3.1 U1.AF17), lmk04828_02 (U15.27)
K2L_JESD_SERDES1_REFCLKN: k2l_soc_08 (K6.1 U1.AF15), lmk04828_02 (U15.30)
K2L_JESD_SERDES1_REFCLKP: k2l_soc_08 (K5.1 U1.AF14), lmk04828_02 (U15.29)
K2L_JESD_TXN0: k2l_soc_08 (U1.AH17), dac38j84_02 (C532.2)
K2L_JESD_TXN1: k2l_soc_08 (U1.AG18), dac38j84_02 (C530.2)
K2L_JESD_TXN2: k2l_soc_08 (U1.AH14), dac38j84_02 (C528.2)
K2L_JESD_TXN3: k2l_soc_08 (U1.AG15), dac38j84_02 (C526.2)
K2L_JESD_TXP0: k2l_soc_08 (U1.AH18), dac38j84_02 (C531.2)
K2L_JESD_TXP1: k2l_soc_08 (U1.AG19), dac38j84_02 (C529.2)
K2L_JESD_TXP2: k2l_soc_08 (U1.AH15), dac38j84_02 (C527.2)
K2L_JESD_TXP3: k2l_soc_08 (U1.AG16), dac38j84_02 (C525.2)
K2L_SYSCLKN: k2l_soc_05 (C2.2), lmk04828_02 (U15.25)
K2L_SYSCLKP: k2l_soc_05 (C1.2), lmk04828_02 (U15.24)
K2L_TIMI0: k2l_soc_06 (R60.1 R68.2), k2l_soc_06_1 (U1.J2)
K2L_TIMI1: k2l_soc_06 (R59.1 R67.2), k2l_soc_06_1 (U1.J1)
K2L_TIMO0: k2l_soc_06 (R62.1 R70.2), k2l_soc_06_1 (U1.H3)
K2L_TIMO1: k2l_soc_06 (R61.1 R69.2), k2l_soc_06_1 (U1.J3)
K2L_VDDCMON: k2l_soc_02 (U1.K10), system_power_01 (R320.2)
K2L_VSSCMON: k2l_soc_02 (U1.K9), system_power_01 (R322.2)
PMBUS_ALERT: system_power_01 (J15.3 R313.1 R329.1), system_power_02 (R334.1), system_power_03 (R360.1)
PMBUS_CLK: system_power_01 (J15.5 R314.1 R328.1), system_power_02 (R332.1), system_power_03 (R358.1)
PMBUS_CNTL: system_power_01 (J15.2 R316.1 R319.1), system_power_02 (R335.1), system_power_03 (R361.1)
PMBUS_DATA: system_power_01 (J15.4 R315.1 R326.1), system_power_02 (R333.1), system_power_03 (R359.1)

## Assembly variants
001: all parts fitted
k2l_adjacent_market_solution_4_default: not fitted C430 C431 C432 C434 C436 C438 C440 R31 R32 R33 R37 R41 R42 R48 R49 R50 R52 R53 R54 R55 R57 R59 R60 R61 R62 R63 R64 R66 R74 R196 R197 R198 R199 R211 R212 R213 R215 R217 R218 R219 R223 R227 R228 R229 R231 R233 R234 R235 R239 R243 R244 R245 R247 R249 R250 R251 R255 R259 R260 R261 R263 R265 R266 R267 R271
